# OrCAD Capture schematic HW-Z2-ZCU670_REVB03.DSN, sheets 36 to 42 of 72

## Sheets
36 037 Clock Generator: size Custom
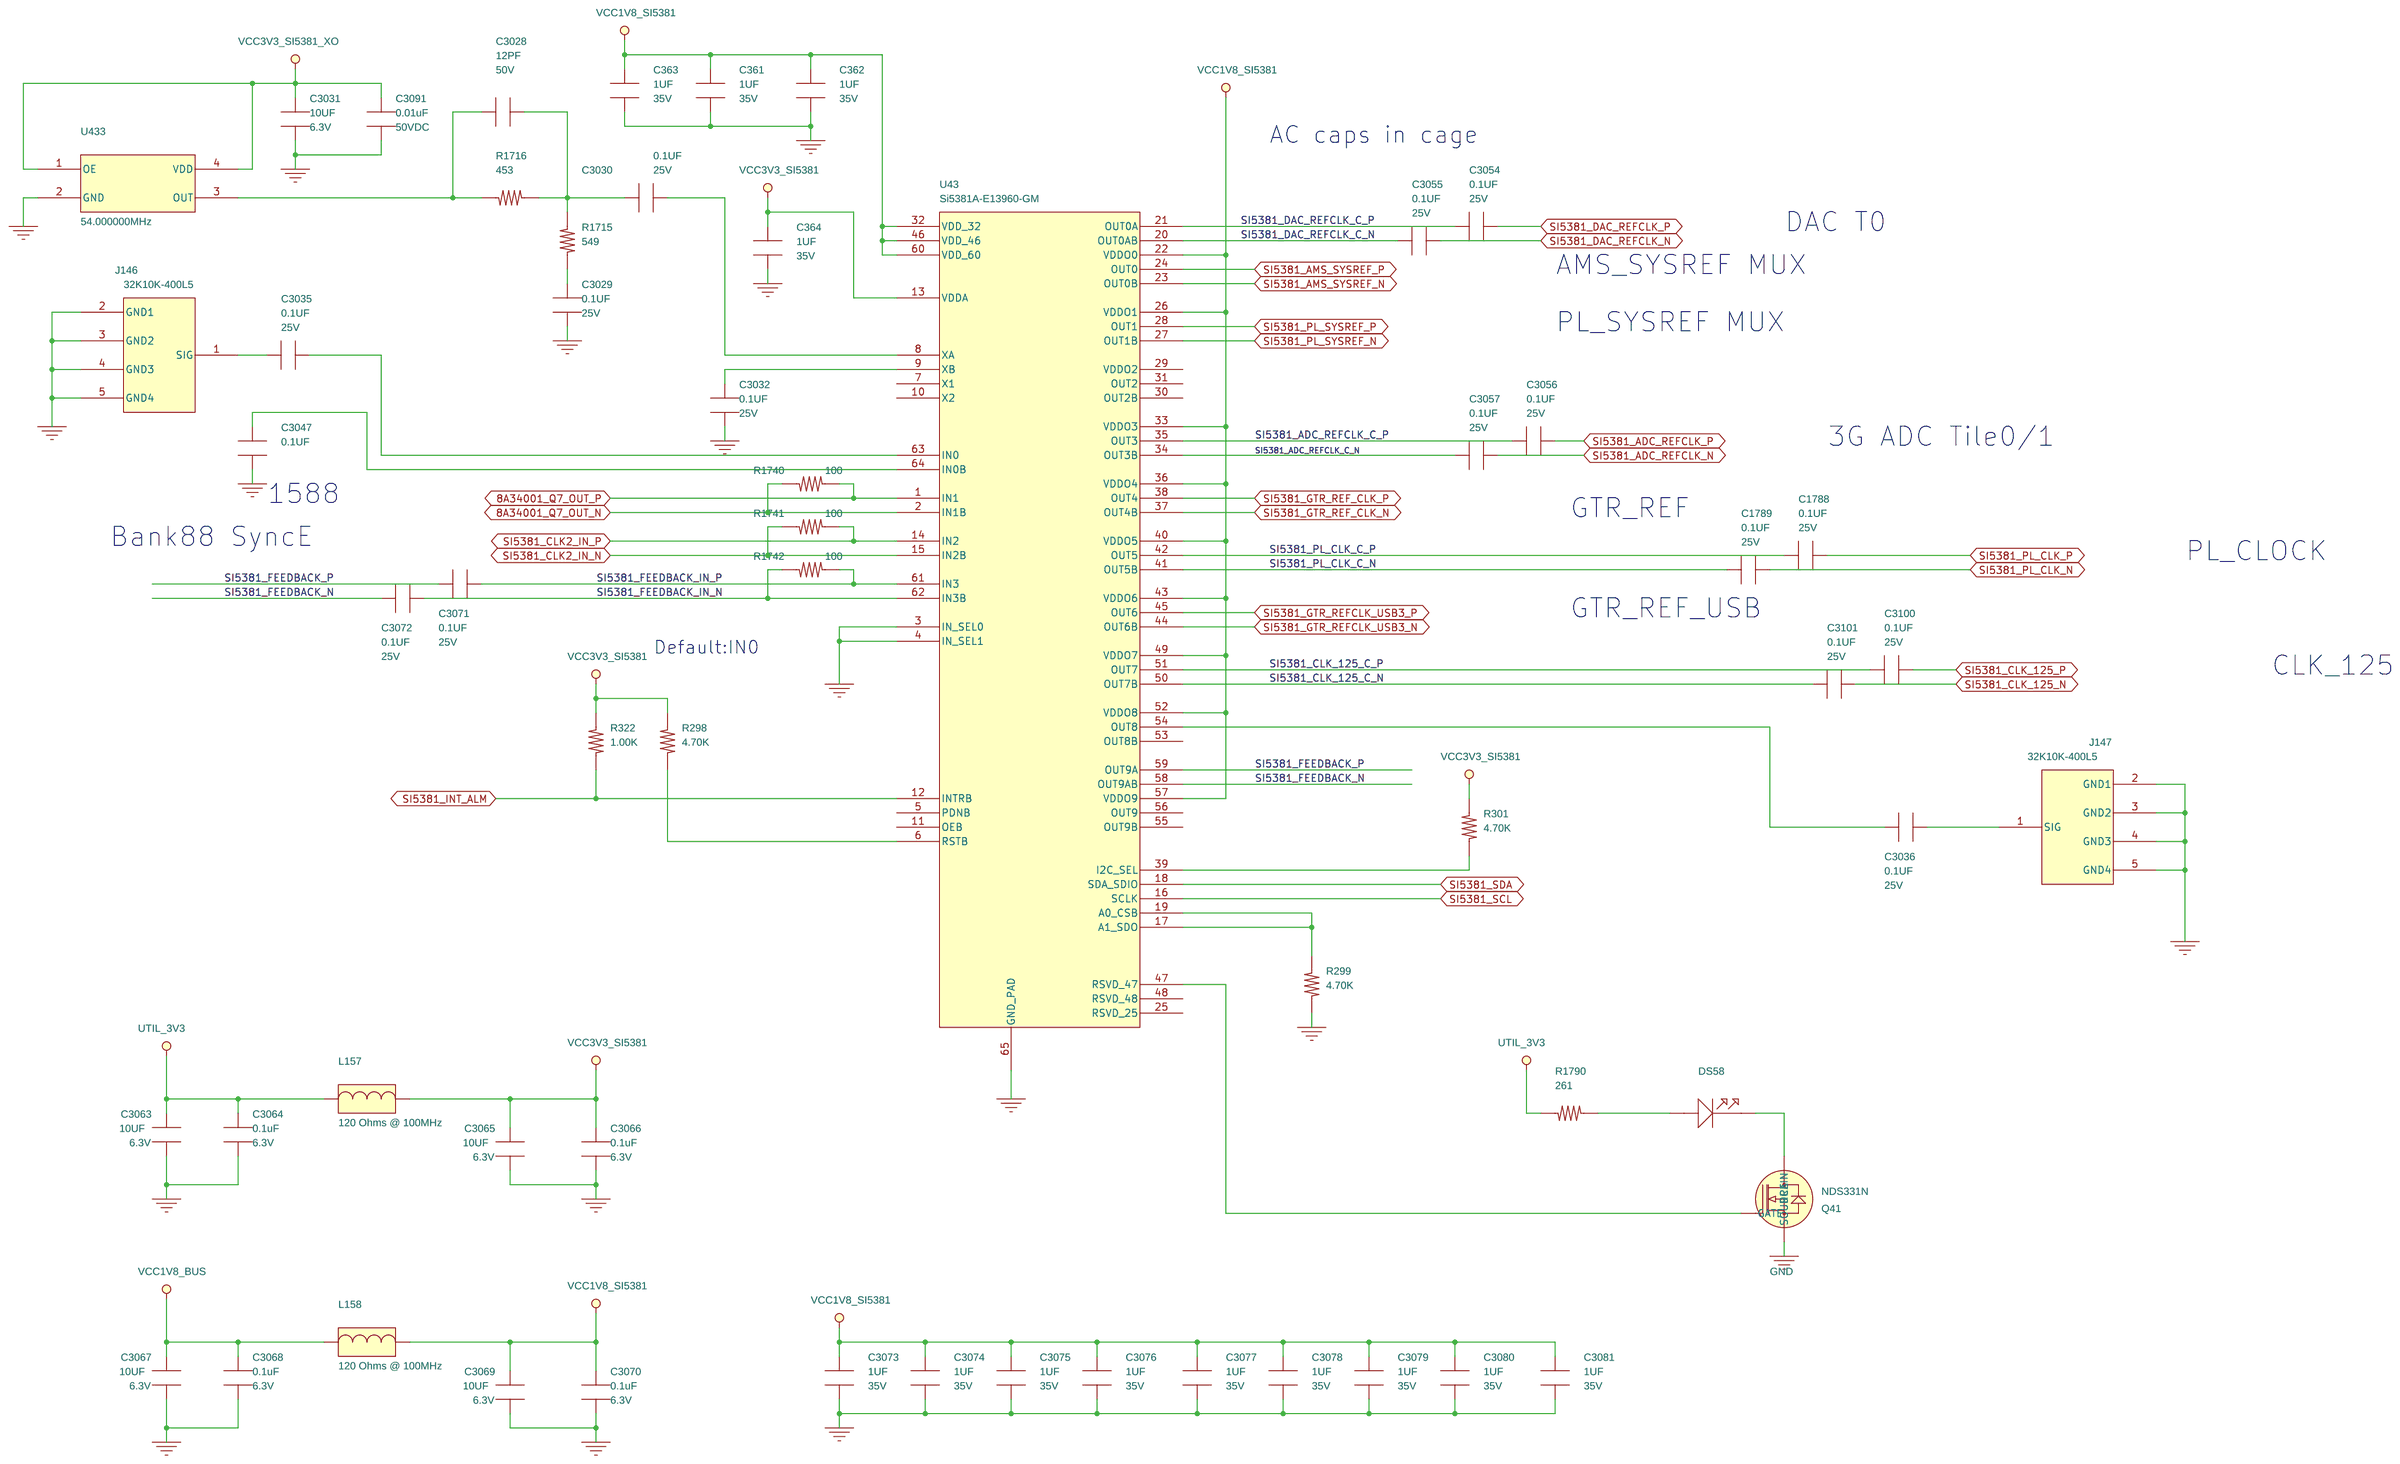
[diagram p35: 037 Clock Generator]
37 042 GPIO Switches Buttons: size Custom
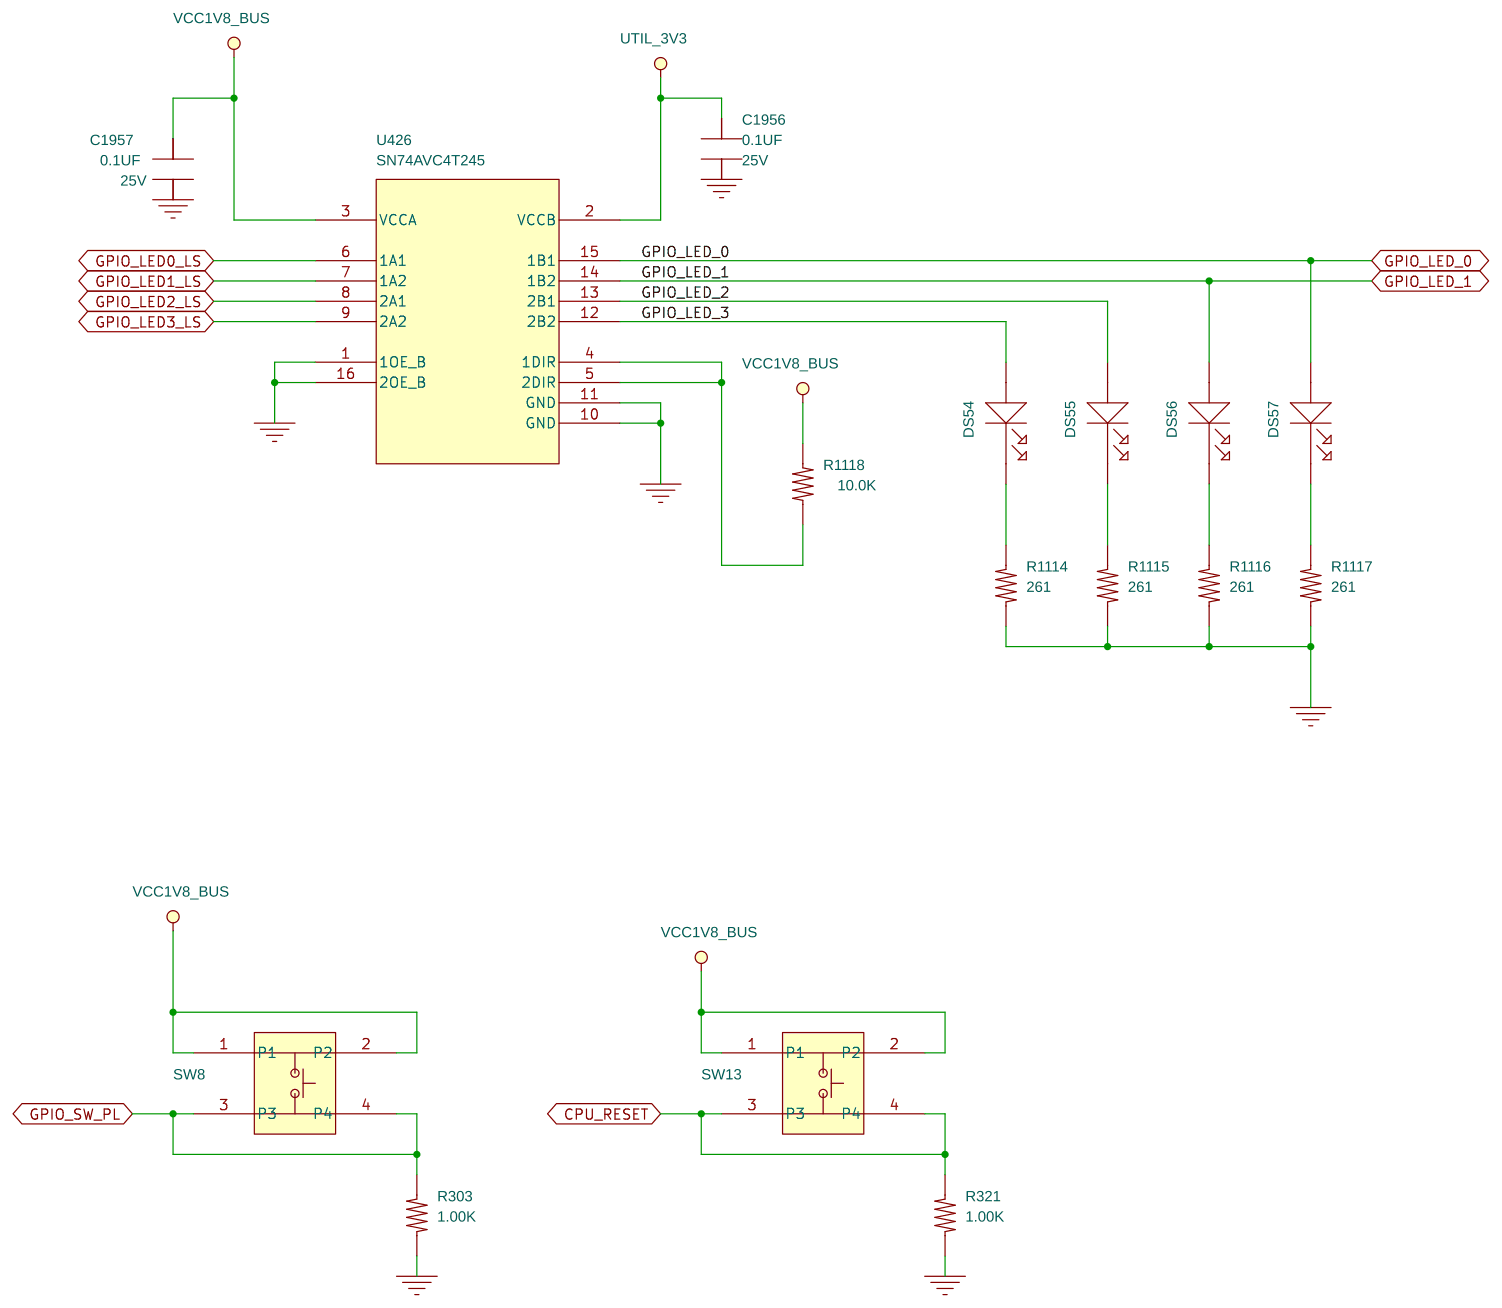
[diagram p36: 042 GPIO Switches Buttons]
38 035 1588 eCPRI CLK 2: size Custom
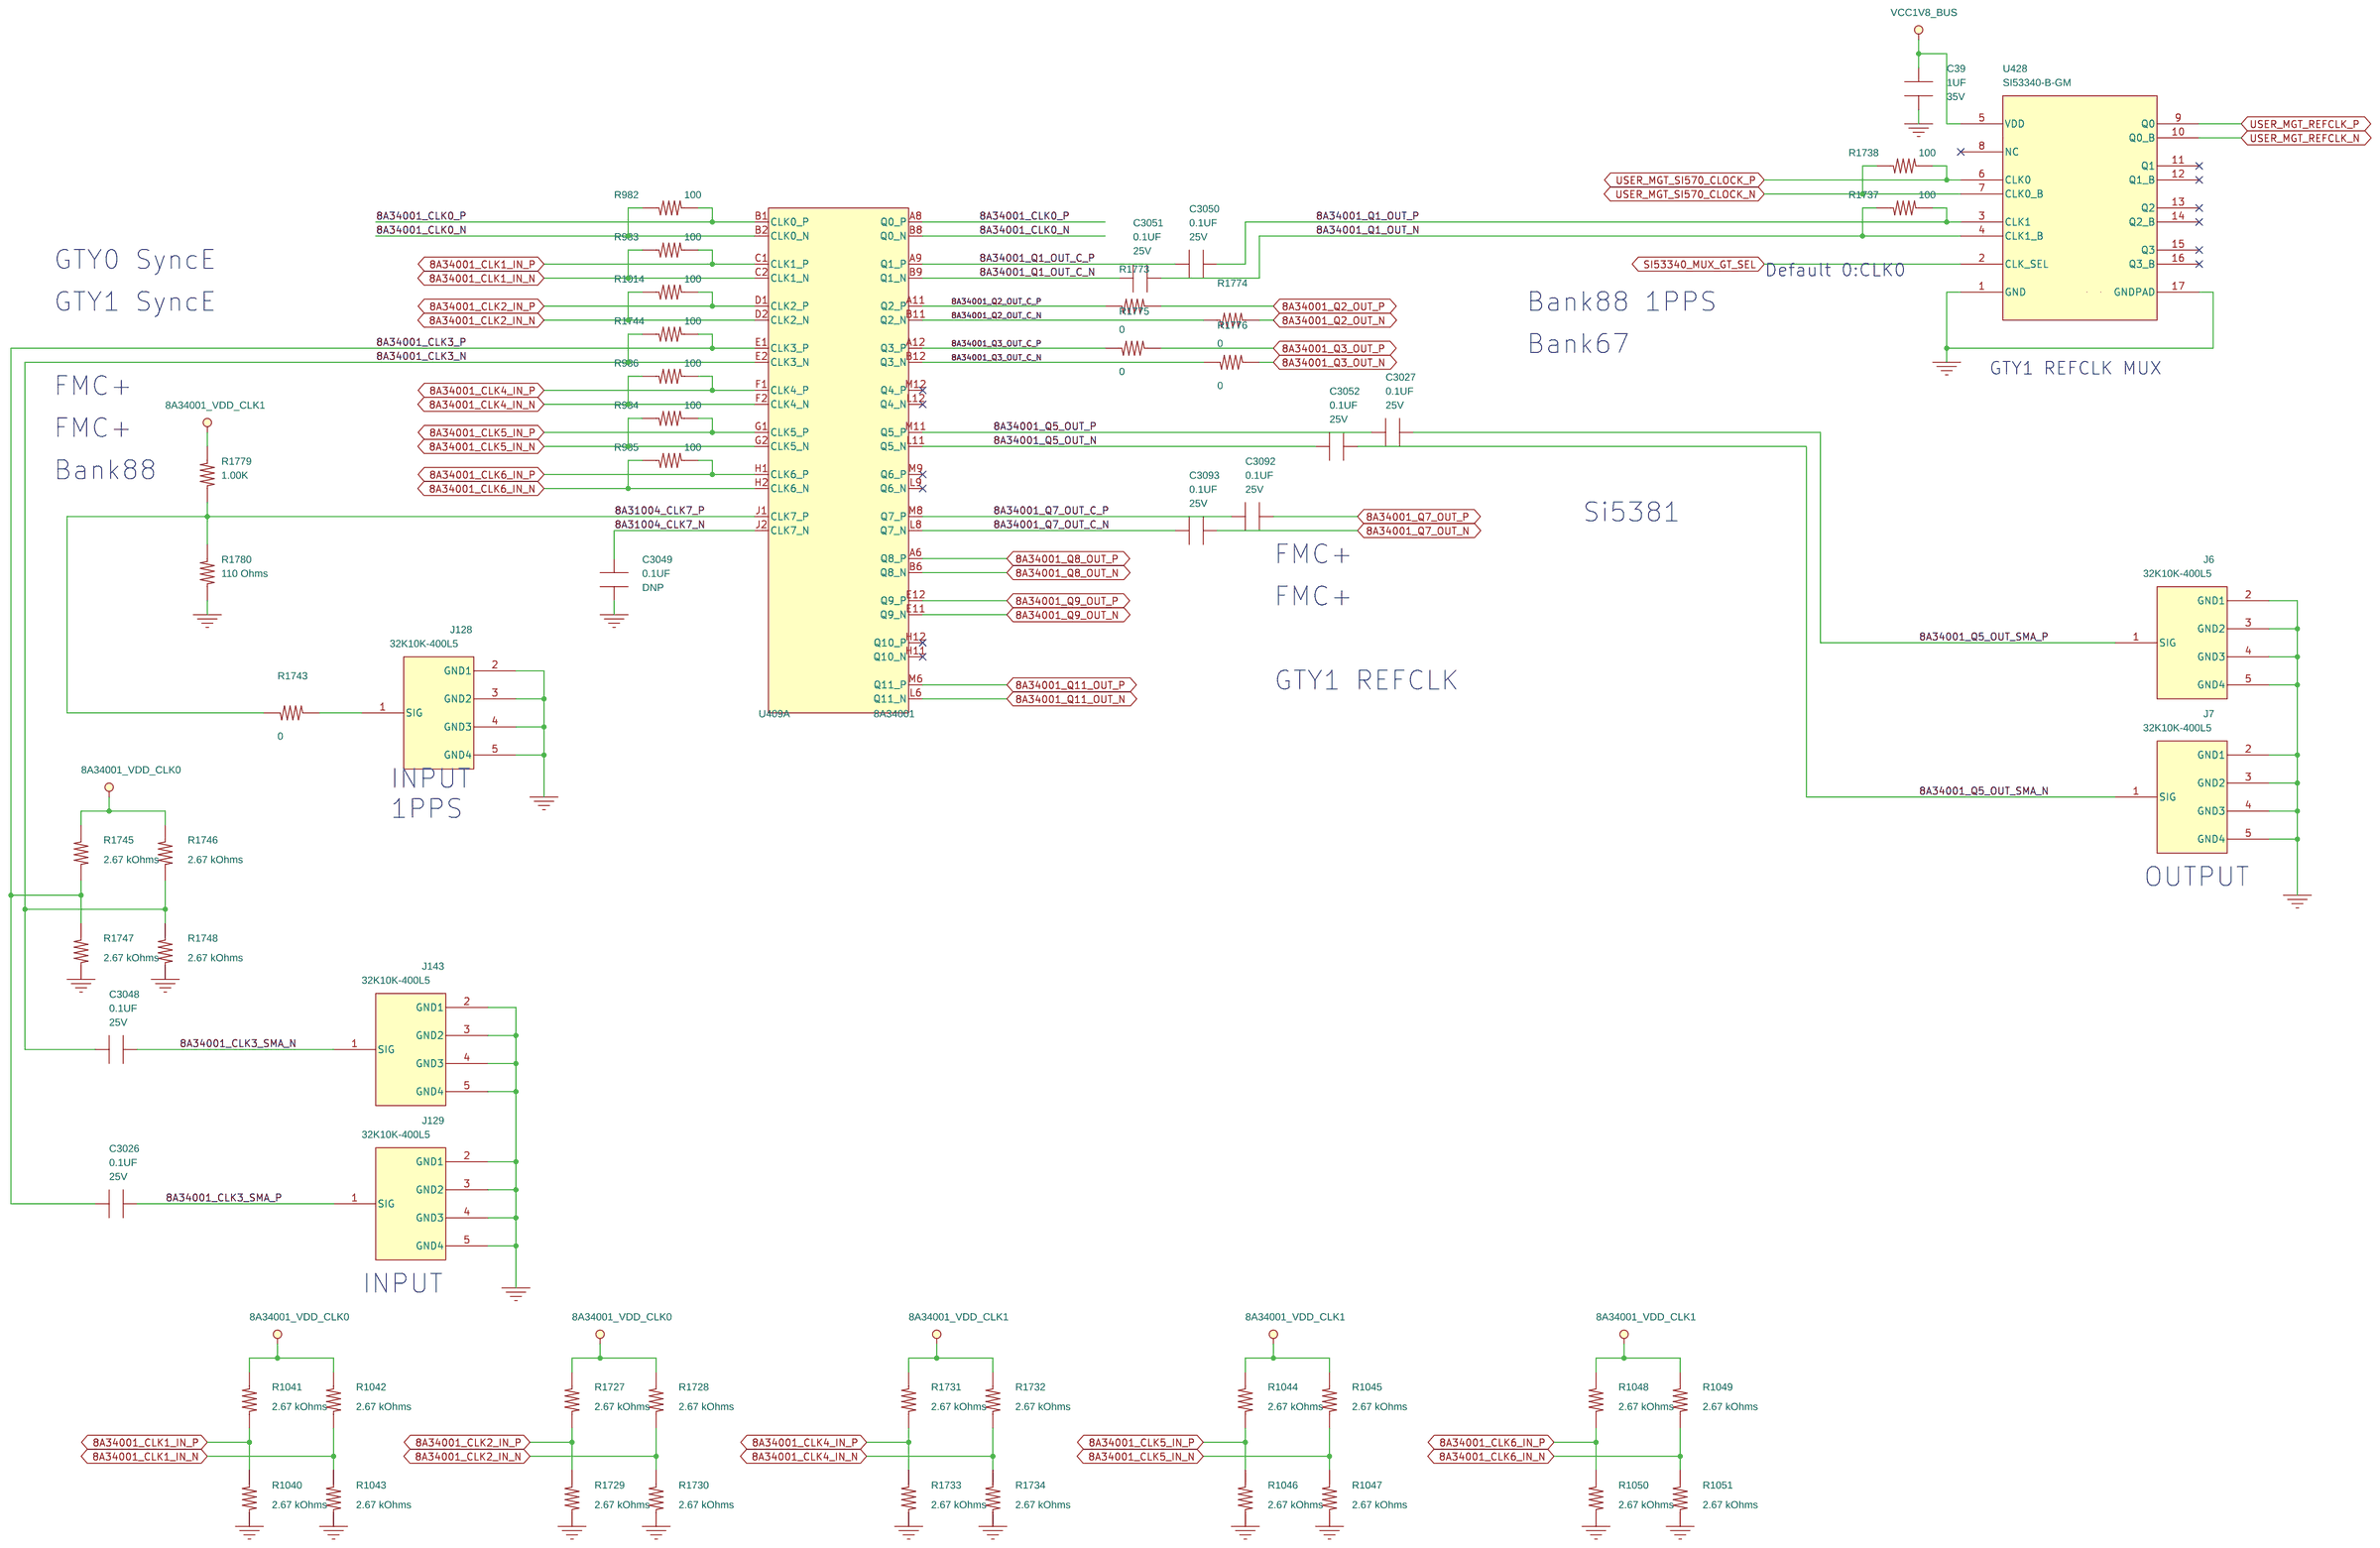
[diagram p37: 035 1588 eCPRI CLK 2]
39 039 Clock SWITCHES: size Custom
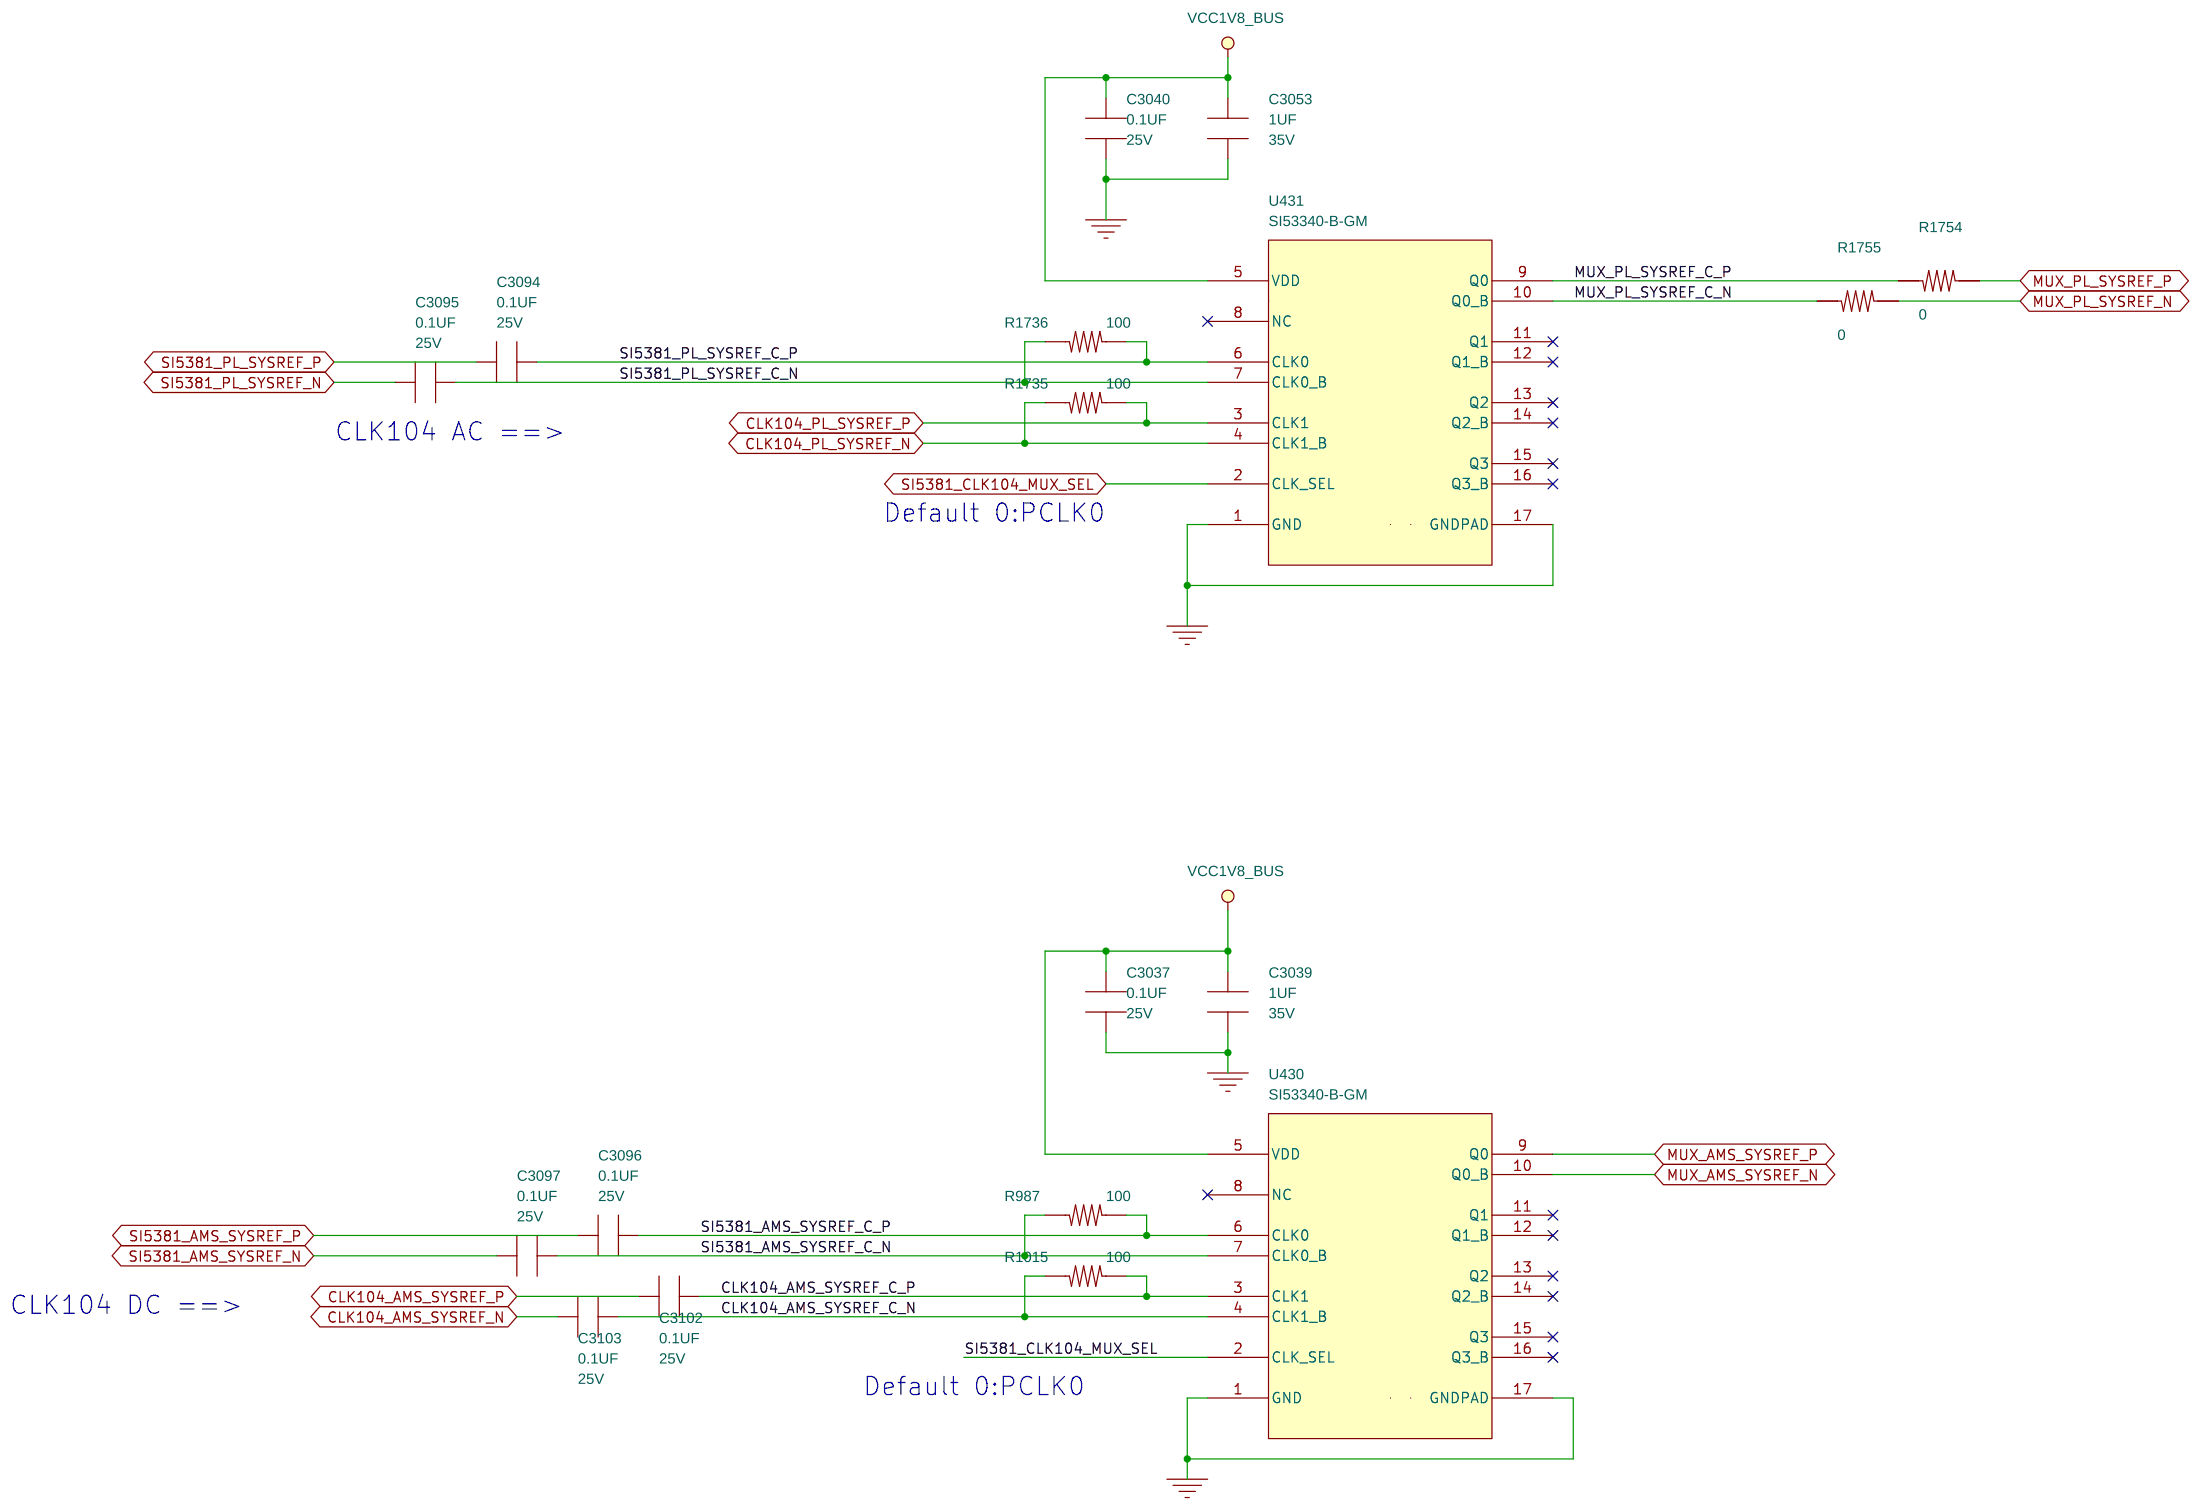
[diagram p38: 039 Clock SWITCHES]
40 040 PS DDR4 SODIMM: size Custom
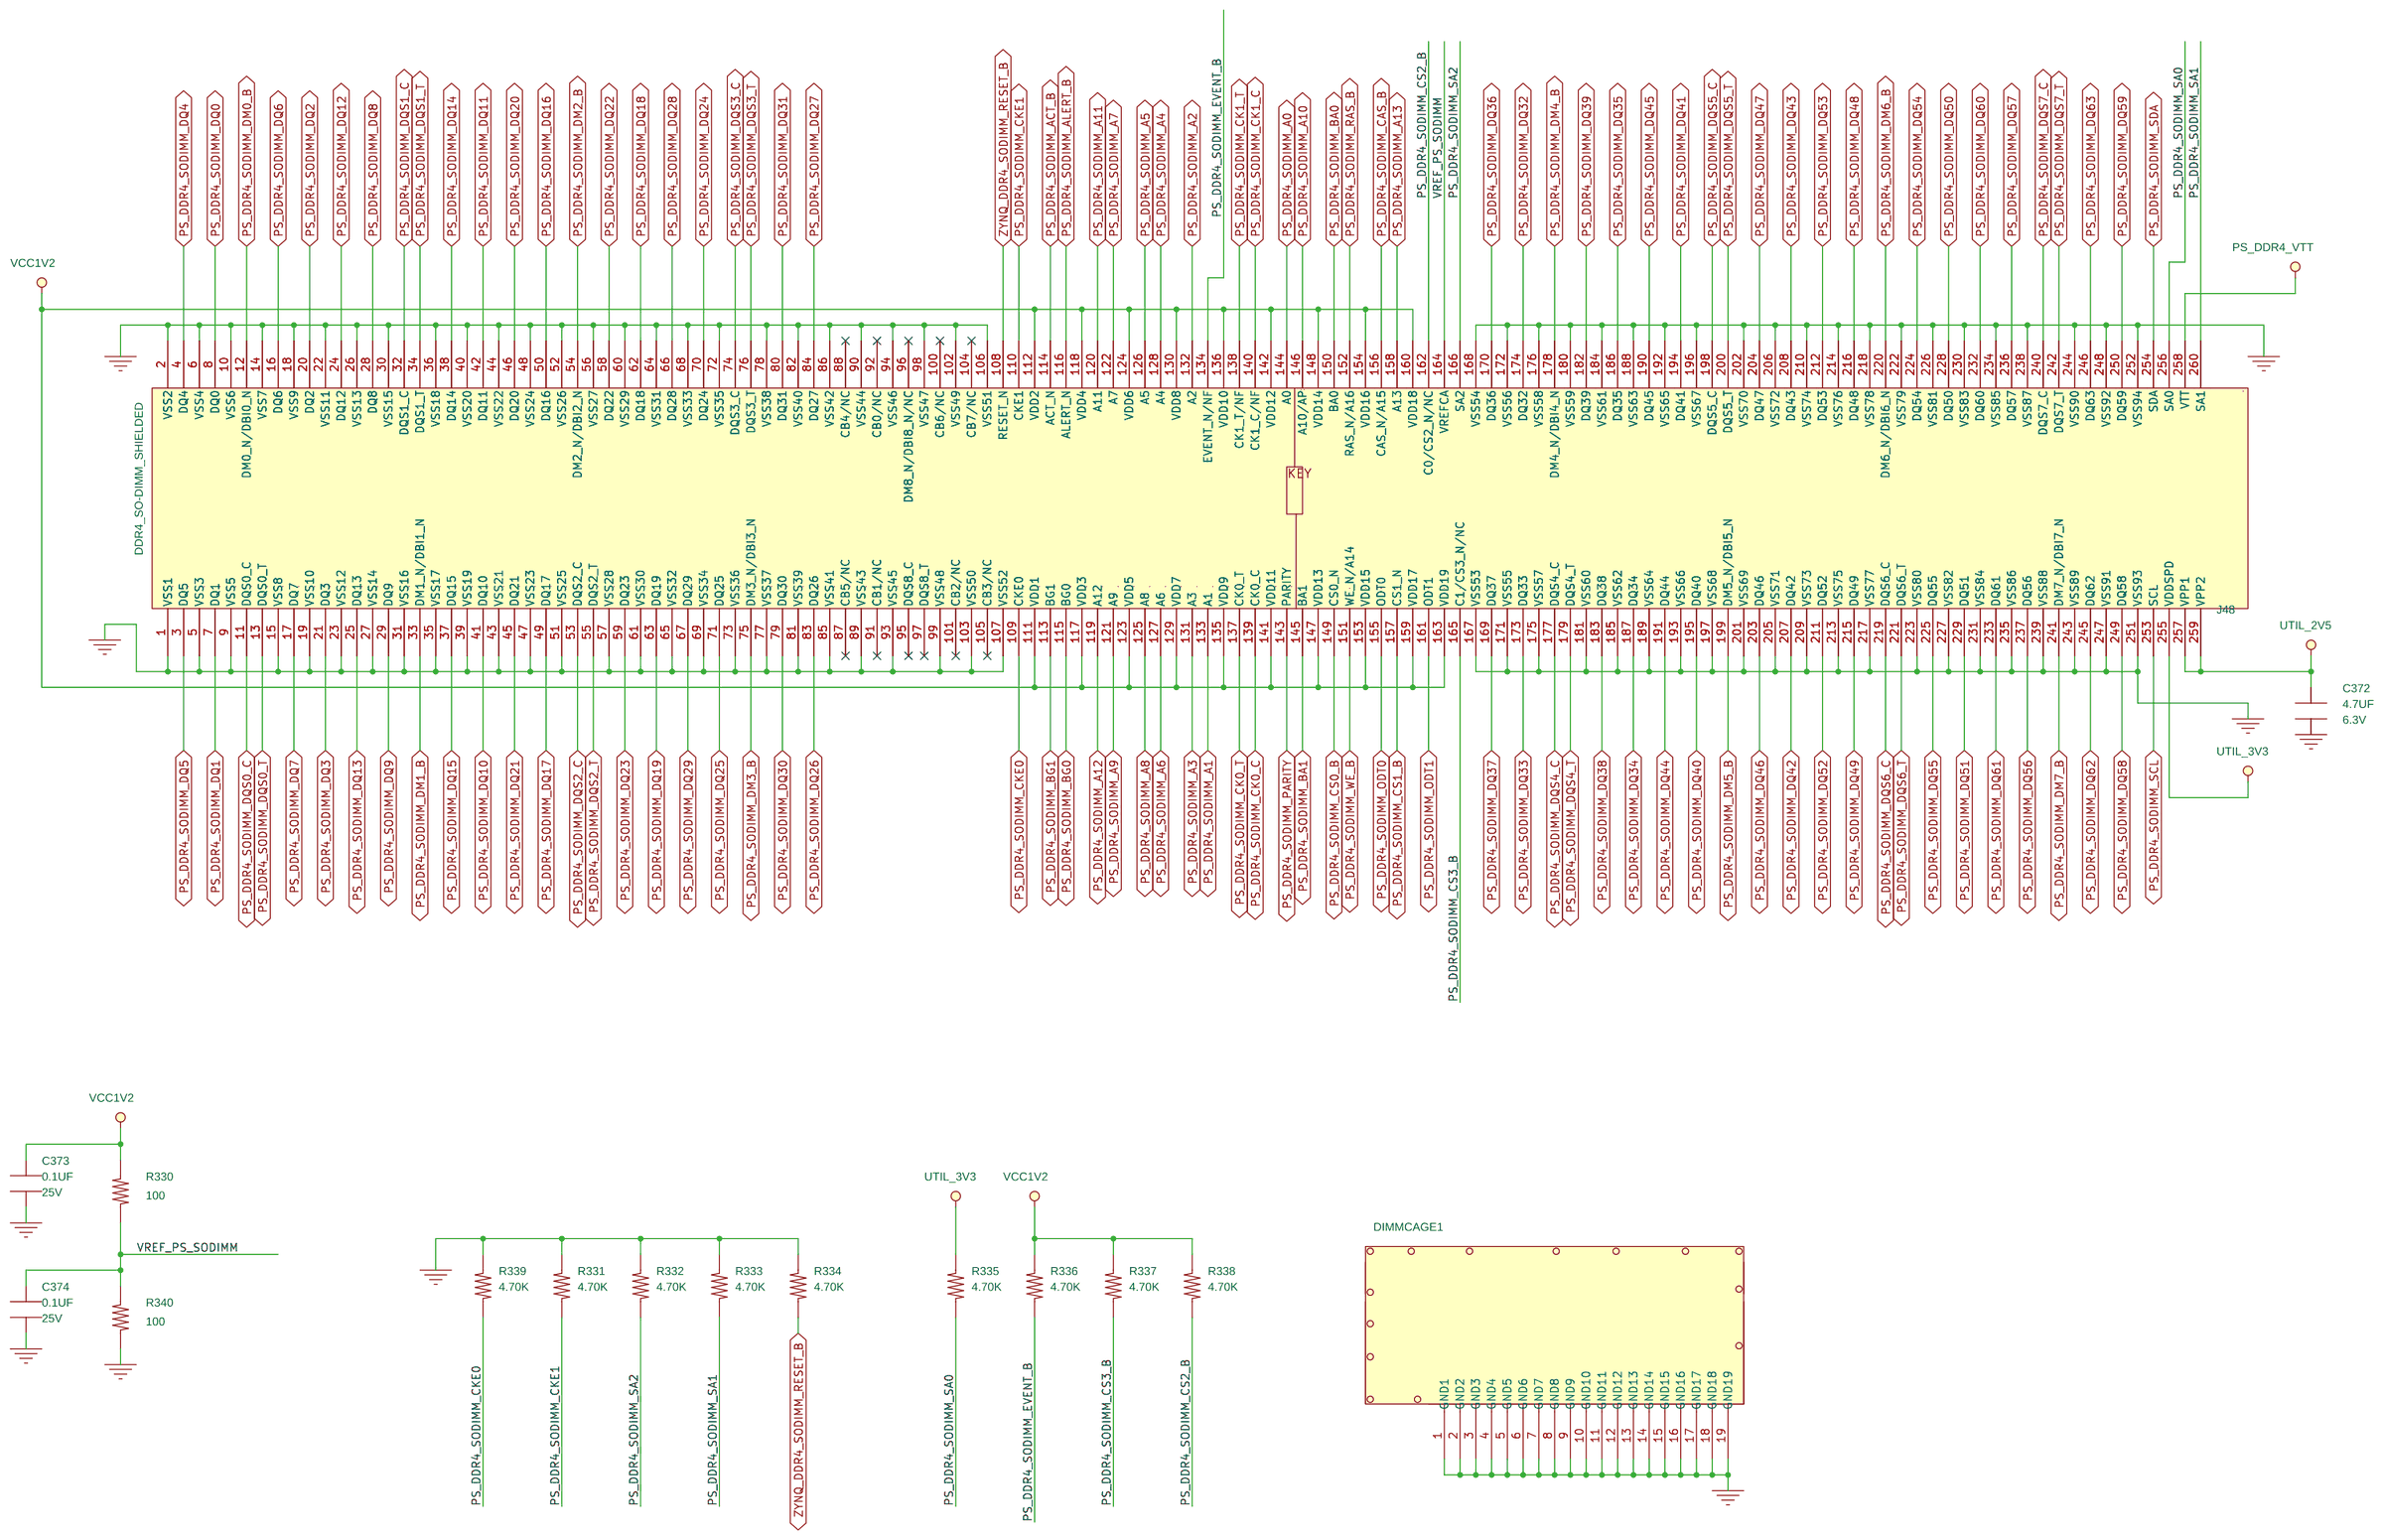
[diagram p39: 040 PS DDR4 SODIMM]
41 041 SODIMM Decoupling: size Custom
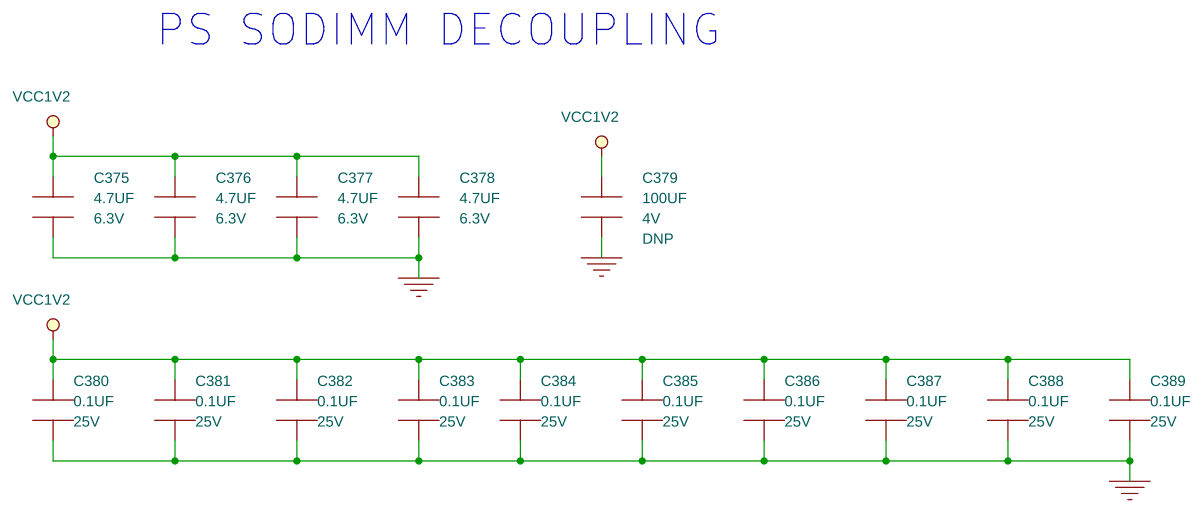
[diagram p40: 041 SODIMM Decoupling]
42 038 Programmable Clocks: size Custom
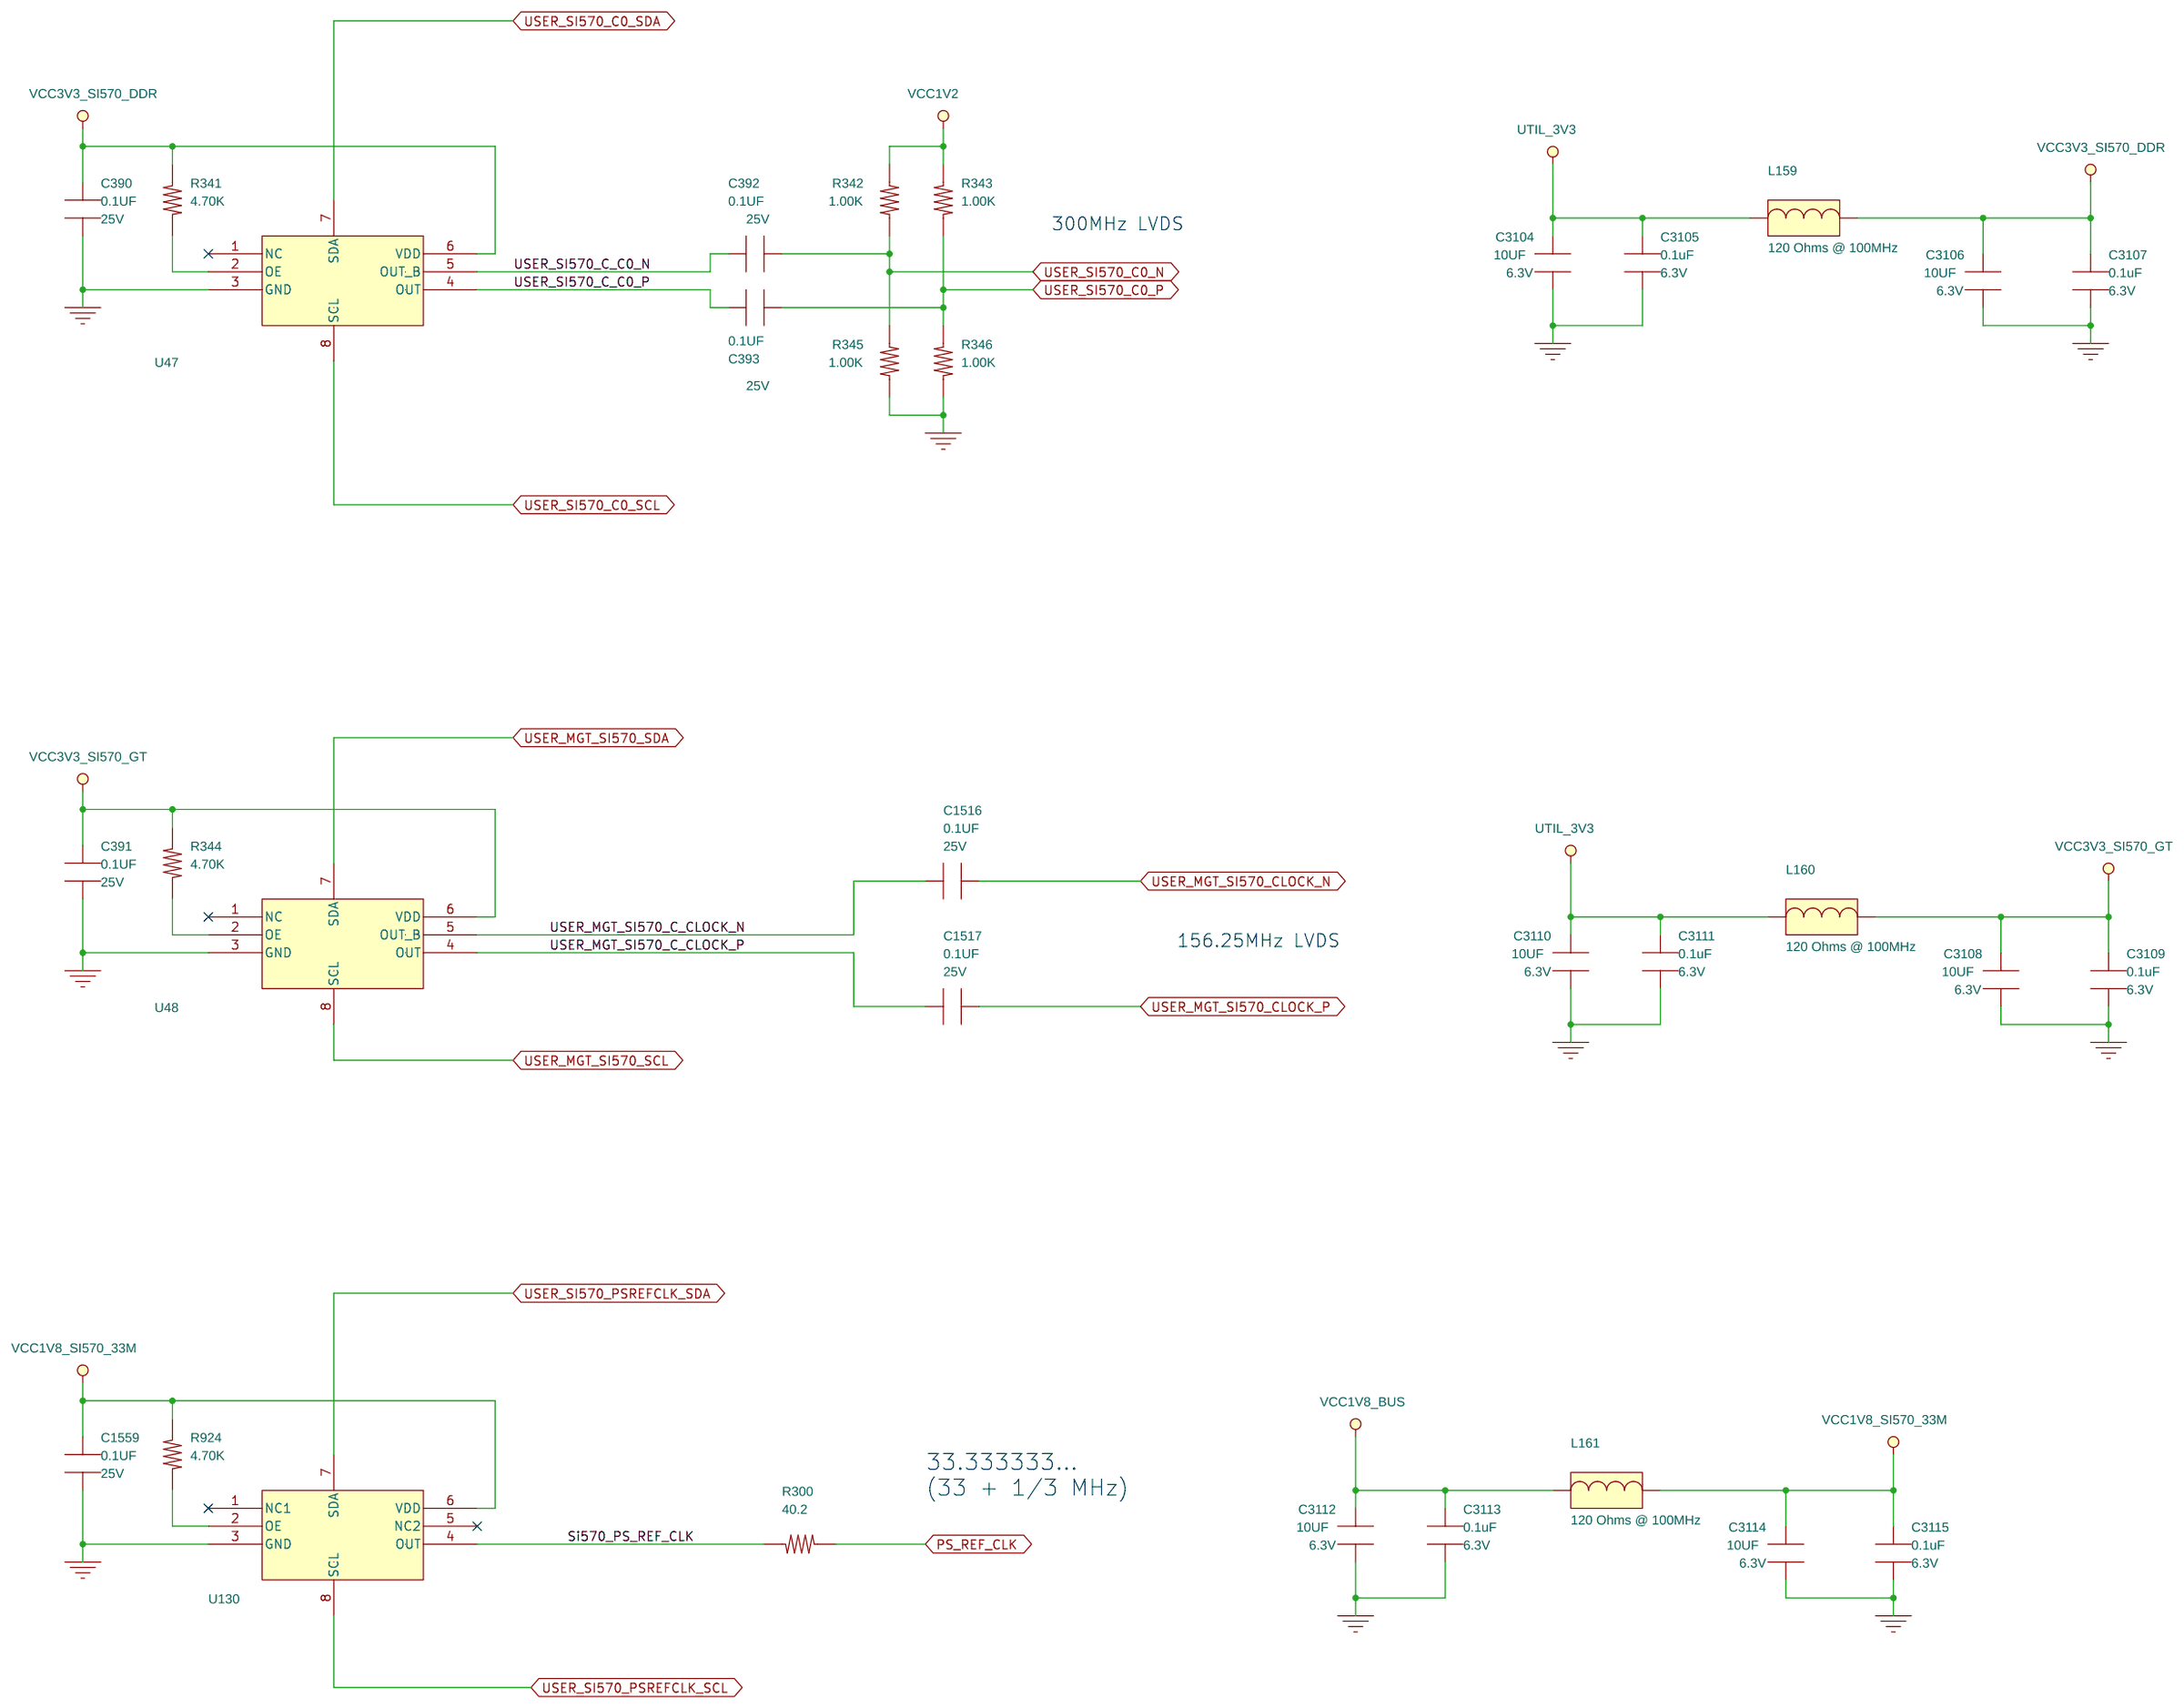
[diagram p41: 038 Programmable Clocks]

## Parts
sheet 035 1588 eCPRI CLK 2
C39  1UF  [CAPC100X50X60]
C3026  0.1UF  [CAPC60X30X40]
C3027  0.1UF  [CAPC60X30X40]
C3048  0.1UF  [CAPC60X30X40]
C3049  0.1UF  [CAPC60X30X40]
C3050  0.1UF  [CAPC60X30X40]
C3051  0.1UF  [CAPC60X30X40]
C3052  0.1UF  [CAPC60X30X40]
C3092  0.1UF  [CAPC60X30X40]
C3093  0.1UF  [CAPC60X30X40]
J6  32K10K-400L5  [32K10K_400_NEW]
J7  32K10K-400L5  [32K10K_400_NEW]
J128  32K10K-400L5  [32K10K_400_NEW]
J129  32K10K-400L5  [32K10K_400_NEW]
J143  32K10K-400L5  [32K10K_400_NEW]
R982  100  [RESC60X30X26]
R983  100  [RESC60X30X26]
R984  100  [RESC60X30X26]
R985  100  [RESC60X30X26]
R986  100  [RESC60X30X26]
R1014  100  [RESC60X30X26]
R1040  2.67 kOhms  [RESC60X30X26]
R1041  2.67 kOhms  [RESC60X30X26]
R1042  2.67 kOhms  [RESC60X30X26]
R1043  2.67 kOhms  [RESC60X30X26]
R1044  2.67 kOhms  [RESC60X30X26]
R1045  2.67 kOhms  [RESC60X30X26]
R1046  2.67 kOhms  [RESC60X30X26]
R1047  2.67 kOhms  [RESC60X30X26]
R1048  2.67 kOhms  [RESC60X30X26]
R1049  2.67 kOhms  [RESC60X30X26]
R1050  2.67 kOhms  [RESC60X30X26]
R1051  2.67 kOhms  [RESC60X30X26]
R1727  2.67 kOhms  [RESC60X30X26]
R1728  2.67 kOhms  [RESC60X30X26]
R1729  2.67 kOhms  [RESC60X30X26]
R1730  2.67 kOhms  [RESC60X30X26]
R1731  2.67 kOhms  [RESC60X30X26]
R1732  2.67 kOhms  [RESC60X30X26]
R1733  2.67 kOhms  [RESC60X30X26]
R1734  2.67 kOhms  [RESC60X30X26]
R1737  100  [RESC60X30X26]
R1738  100  [RESC60X30X26]
R1743  0  [RESC60X30X26]
R1744  100  [RESC60X30X26]
R1745  2.67 kOhms  [RESC60X30X26]
R1746  2.67 kOhms  [RESC60X30X26]
R1747  2.67 kOhms  [RESC60X30X26]
R1748  2.67 kOhms  [RESC60X30X26]
R1773  0  [RESC60X30X26]
R1774  0  [RESC60X30X26]
R1775  0  [RESC60X30X26]
R1776  0  [RESC60X30X26]
R1779  1.00K  [RESC100X50X40]
R1780  110 Ohms  [RESC100X50X40]
U409  8A34001  [CABGA_144P80]  (sections A,B,C)
U428  SI53340-B-GM  [QFN16_SI_3X3MM]
sheet 037 Clock Generator
C361  1UF  [CAPC100X50X60]
C362  1UF  [CAPC100X50X60]
C363  1UF  [CAPC100X50X60]
C364  1UF  [CAPC100X50X60]
C1788  0.1UF  [CAPC60X30X40]
C1789  0.1UF  [CAPC60X30X40]
C3028  12PF  [CAPC100X50X55]
C3029  0.1UF  [CAPC100X50X55]
C3030  0.1UF  [CAPC100X50X55]
C3031  10UF  [CAPC100X50X70]
C3032  0.1UF  [CAPC100X50X55]
C3035  0.1UF  [CAPC60X30X40]
C3036  0.1UF  [CAPC60X30X40]
C3047  0.1UF  [CAPC60X30X40]
C3054  0.1UF  [CAPC60X30X40]
C3055  0.1UF  [CAPC60X30X40]
C3056  0.1UF  [CAPC60X30X40]
C3057  0.1UF  [CAPC60X30X40]
C3063  10UF  [CAPC100X50X70]
C3064  0.1uF  [CAPC60X30X33]
C3065  10UF  [CAPC100X50X70]
C3066  0.1uF  [CAPC60X30X33]
C3067  10UF  [CAPC100X50X70]
C3068  0.1uF  [CAPC60X30X33]
C3069  10UF  [CAPC100X50X70]
C3070  0.1uF  [CAPC60X30X33]
C3071  0.1UF  [CAPC60X30X40]
C3072  0.1UF  [CAPC60X30X40]
C3073  1UF  [CAPC100X50X60]
C3074  1UF  [CAPC100X50X60]
C3075  1UF  [CAPC100X50X60]
C3076  1UF  [CAPC100X50X60]
C3077  1UF  [CAPC100X50X60]
C3078  1UF  [CAPC100X50X60]
C3079  1UF  [CAPC100X50X60]
C3080  1UF  [CAPC100X50X60]
C3081  1UF  [CAPC100X50X60]
C3091  0.01uF  [CAPC100X50X55]
C3100  0.1UF  [CAPC60X30X40]
C3101  0.1UF  [CAPC60X30X40]
DS58  LED-GRN-SMT  [LED_0603]
J146  32K10K-400L5  [32K10K_400_NEW]
J147  32K10K-400L5  [32K10K_400_NEW]
L157  120 Ohms @ 100MHz  [FB_BLM15PX121SN1D]
L158  120 Ohms @ 100MHz  [FB_BLM15PX121SN1D]
Q41  NDS331N  [SOT_23]
R298  4.70K  [RESC100X50X40]
R299  4.70K  [RESC100X50X40]
R301  4.70K  [RESC100X50X40]
R322  1.00K  [RESC100X50X40]
R1715  549  [RESC100X50X40]
R1716  453  [RESC100X50X40]
R1740  100  [RESC60X30X26]
R1741  100  [RESC60X30X26]
R1742  100  [RESC60X30X26]
R1790  261  [RESC100X50X40]
U43  Si5381A-E13960-GM  [OSC_SI341B_64P]
U433  54.000000MHz  [OSC320X250X110-4]
sheet 038 Programmable Clocks
C390  0.1UF  [CAPC100X50X55]
C391  0.1UF  [CAPC100X50X55]
C392  0.1UF  [CAPC100X50X55]
C393  0.1UF  [CAPC100X50X55]
C1516  0.1UF  [CAPC100X50X55]
C1517  0.1UF  [CAPC100X50X55]
C1559  0.1UF  [CAPC100X50X55]
C3104  10UF  [CAPC100X50X70]
C3105  0.1uF  [CAPC60X30X33]
C3106  10UF  [CAPC100X50X70]
C3107  0.1uF  [CAPC60X30X33]
C3108  10UF  [CAPC100X50X70]
C3109  0.1uF  [CAPC60X30X33]
C3110  10UF  [CAPC100X50X70]
C3111  0.1uF  [CAPC60X30X33]
C3112  10UF  [CAPC100X50X70]
C3113  0.1uF  [CAPC60X30X33]
C3114  10UF  [CAPC100X50X70]
C3115  0.1uF  [CAPC60X30X33]
L159  120 Ohms @ 100MHz  [FB_BLM15PX121SN1D]
L160  120 Ohms @ 100MHz  [FB_BLM15PX121SN1D]
L161  120 Ohms @ 100MHz  [FB_BLM15PX121SN1D]
R300  40.2  [RESC100X50X40]
R341  4.70K  [RESC100X50X40]
R342  1.00K  [RESC100X50X40]
R343  1.00K  [RESC100X50X40]
R344  4.70K  [RESC100X50X40]
R345  1.00K  [RESC100X50X40]
R346  1.00K  [RESC100X50X40]
R924  4.70K  [RESC100X50X40]
U47  10MHZ_TO_810MHZ  [SI570]
U48  10MHZ_TO_810MHZ  [SI570]
U130  10MHZ-160MHZ  [SI570]
sheet 039 Clock SWITCHES
C3037  0.1UF  [CAPC100X50X55]
C3039  1UF  [CAPC100X50X60]
C3040  0.1UF  [CAPC100X50X55]
C3053  1UF  [CAPC100X50X60]
C3094  0.1UF  [CAPC60X30X40]
C3095  0.1UF  [CAPC60X30X40]
C3096  0.1UF  [CAPC60X30X40]
C3097  0.1UF  [CAPC60X30X40]
C3102  0.1UF  [CAPC60X30X40]
C3103  0.1UF  [CAPC60X30X40]
R987  100  [RESC60X30X26]
R1015  100  [RESC60X30X26]
R1735  100  [RESC60X30X26]
R1736  100  [RESC60X30X26]
R1754  0  [RESC60X30X26]
R1755  0  [RESC60X30X26]
U430  SI53340-B-GM  [QFN16_SI_3X3MM]
U431  SI53340-B-GM  [QFN16_SI_3X3MM]
sheet 040 PS DDR4 SODIMM
C372  4.7UF  [CAPC100X50X60]
C373  0.1UF  [CAPC100X50X55]
C374  0.1UF  [CAPC100X50X55]
DIMMCAGE1  SODIMM_CAGE  [SODIMM_CAGE]
J48  DDR4_SO-DIMM_SHIELDED  [DDR4_SO-DIMM_SHIELDED]
R330  100  [RESC100X50X40]
R331  4.70K  [RESC100X50X40]
R332  4.70K  [RESC100X50X40]
R333  4.70K  [RESC100X50X40]
R334  4.70K  [RESC100X50X40]
R335  4.70K  [RESC100X50X40]
R336  4.70K  [RESC100X50X40]
R337  4.70K  [RESC100X50X40]
R338  4.70K  [RESC100X50X40]
R339  4.70K  [RESC100X50X40]
R340  100  [RESC100X50X40]
sheet 041 SODIMM Decoupling
C375  4.7UF  [CAPC100X50X60]
C376  4.7UF  [CAPC100X50X60]
C377  4.7UF  [CAPC100X50X60]
C378  4.7UF  [CAPC100X50X60]
C379  100UF  [CAPC200X125X145]
C380  0.1UF  [CAPC100X50X55]
C381  0.1UF  [CAPC100X50X55]
C382  0.1UF  [CAPC100X50X55]
C383  0.1UF  [CAPC100X50X55]
C384  0.1UF  [CAPC100X50X55]
C385  0.1UF  [CAPC100X50X55]
C386  0.1UF  [CAPC100X50X55]
C387  0.1UF  [CAPC100X50X55]
C388  0.1UF  [CAPC100X50X55]
C389  0.1UF  [CAPC100X50X55]
sheet 042 GPIO Switches Buttons
C1956  0.1UF  [CAPC100X50X55]
C1957  0.1UF  [CAPC100X50X55]
DS54  LED-GRN-SMT  [LED_0603]
DS55  LED-GRN-SMT  [LED_0603]
DS56  LED-GRN-SMT  [LED_0603]
DS57  LED-GRN-SMT  [LED_0603]
R303  1.00K  [RESC100X50X40]
R321  1.00K  [RESC100X50X40]
R1114  261  [RESC100X50X40]
R1115  261  [RESC100X50X40]
R1116  261  [RESC100X50X40]
R1117  261  [RESC100X50X40]
R1118  10.0K  [RESC100X50X40]
SW8  TL3301EF100QG  [SW_TL3301_G_4P]
SW13  TL3301EF100QG  [SW_TL3301_G_4P]
U426  SN74AVC4T245  [QFN_RSV_16]

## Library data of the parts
C39 C361-C364 C3039 C3053 C3073-C3081 = CAP_NP: Cap Cer 1uF 10% 35V X5R 0402; ALT_SYMBOLS: CAPC100X50X60RND; Agile Part Number: CAP-00165-01; CIP Link: http://xsjbrdwin1/CIP-E/Component/Index/All?pn=100192; Dielectric Type: X5R; OWNER: 3709; PRICE: 0.04; Part Type: CERAMIC; PartType: CERAMIC; ROHS: Yes; Tolerance: 10%; Voltage: 35V; barcode: 100192
C1788 C1789 C3026 C3027 C3035 C3036 C3048 C3050-C3052 C3054-C3057 C3071 C3072 C3092-C3097 C3100-C3103 = CAP_NP: Cap Cer 100nF 10% 25V X5R 0201; ALT_SYMBOLS: CAPC60X30X40RND; Agile Part Number: CAP-00142-01; Barcode: 100161; CIP Link: http://xsjbrdwin1/CIP-E/Component/Index/All?pn=100161; Dielectric Type: X5R; Part Type: CERAMIC; Tolerance: 10%; Voltage: 25V
C3049 = CAP_NP: Cap Cer 100nF 10% 25V X5R 0201; ALT_SYMBOLS: CAPC60X30X40RND; ASSEMBLY_OPTIONS: DNP; Agile Part Number: CAP-00142-01; Barcode: 100161; CIP Link: http://xsjbrdwin1/CIP-E/Component/Index/All?pn=100161; Dielectric Type: X5R; Part Type: CERAMIC; Tolerance: 10%; Voltage: 25V
J6 J7 J128 J129 J143 J146 J147 = SMA-5PIN: Conn Rcpt SMA Vert 50R 12.4GHz SMT/TH; ALT_SYMBOLS: 32K10K_400_3M_73251_DUAL; Agile Part Number: CON-00180-01; Barcode: 400125; CIP Link: http://xsjbrdwin1/CIP-E/Component/Index/All?pn=400125; OWNER: 4001; PRICE: 3.89; Part Type: SMA; PartType: SMA; Pins: 5PINS; ROHS: Yes
R982-R987 R1014 R1015 R1735-R1738 R1740-R1742 R1744 = RES: Res 100R 1% 1/20W 200PPM 25V 0201; Agile Part Number: RES-00129-01; Barcode: 200116; CIP Link: http://xsjbrdwin1/CIP-E/Component/Index/All?pn=200116; Part Type: SMT - 1%; Rated Power: 1/20W; Tolerance: 1%
R1040-R1051 R1727-R1734 R1745-R1748 = RES: Res 2K67 1% 1/20W 200PPM 25V 0201; Agile Part Number: RES-00598-01; Barcode: 20000076; CIP Link: http://xsjbrdwin1/CIP-E/Component/Index/All?pn=20000076; Part Type: SMT - 1%; Rated Power: 0.05W, 1/20W; Tolerance: 1%
R1743 R1754 R1755 R1773-R1776 = RES: Res 0R 50mR 500mA 0201; ALT_SYMBOLS: RESC60X30X26RND; Agile Part Number: RES-00347-01; Barcode: 200383; CIP Link: http://xsjbrdwin1/CIP-E/Component/Index/All?pn=200383; Part Type: RESISTOR; Rated Power: 1/20W; Tolerance: NA
R303 R321 R322 R342 R343 R345 R346 R1779 = RES: Res 1K 1% 1/16W 100PPM 50V 0402; ALT_SYMBOLS: RESC100X50X40RND; Agile Part Number: RES-00027-01; Barcode: 200098; CIP Link: http://xsjbrdwin1/CIP-E/Component/Index/All?pn=200098; OWNER: 4001; PRICE: 0; Part Type: SMT - 1%; PartType: SMT - 1%; Power: 1/16W; ROHS: Yes; Rated Power: 1/16W; Tolerance: 1%; primarykey: 7
R1780 = RES: Res 110R 1% 1/16W 100PPM 50V 0402; Agile Part Number: RES-00511-01; Barcode: 20000030; CIP Link: http://xsjbrdwin1/CIP-E/Component/Index/All?pn=20000030; Part Type: SMT - 1%; Rated Power: 1/16W; Tolerance: 1%
U409 = 8A34001: IC Synch Man Unit 8-Ch 24 LVCMOS Outs CABGA-144; Agile Part Number: ICS-00510-01; Barcode: 50000042; CIP Link: http://xsjbrdwin1/CIP-E/Component/Index/All?pn=50000042; Part Type: Unassigned Part Type
U428 U430 U431 = SI53340: IC BUFFER 2:4 LVDS MUX 16QFN; Agile Part Number: ICS-00217-01; Barcode: 500294; CIP Link: http://xsjbrdwin1/CIP-E/Component/Index/All?pn=500294; Part Type: CLOCK MULTIPLIER
C3028 = CAP_NP: Cap Cer 12pF 5% 50V C0G 0402; ALT_SYMBOLS: (0402,C402-25,CAPC100X50X55L25NRND,CAPC100X50X55L30NRND,CAPC100X50X55L30N); Agile Part Number: CAP-00095-01; Barcode: 100092; CIP Link: http://xsjbrdwin1/CIP-E/Component/Index/All?pn=100092; Dielectric Type: NP0; Part Type: CERAMIC; Tolerance: 5%; Voltage: 50V
C373 C374 C380-C393 C1559 C1956 C1957 C3029 C3030 C3032 C3037 C3040 = CAP_NP: Cap Cer 100nF 10% 25V X5R 0402; ALT_SYMBOLS: CAPC100X50X55RND; Agile Part Number: CAP-00068-01; CIP Link: http://xsjbrdwin1/CIP-E/Component/Index/All?pn=100040; Dielectric Type: X5R; OWNER: 4001; PRICE: 0.01; Part Type: CERAMIC; PartType: CERAMIC; ROHS: Yes; Tolerance: 10%; Voltage: 25V; barcode: 100040
C3031 = CAP_NP: Cap Cer 10uF 20%  6.3V X6S 0402; ALT_SYMBOLS: CAPC100X50X55RND; Agile Part Number: CAP-00035-01; CIP Link: http://xsjbrdwin1/CIP-E/Component/Index/All?pn=100268; Dielectric Type: X6S; OWNER: 3670; PRICE: 0.04; Part Type: CERAMIC; PartType: CERAMIC; ROHS: Yes; Tolerance: 20%; Voltage: 6.3V; barcode: 100268
C3047 = CAP_NP: Cap Cer 100nF 10% 25V X5R 0201; ALT_SYMBOLS: CAPC60X30X40RND; ASSEMBLY_OPTIONS: <ASSEMBLY_OPTIONS>; Agile Part Number: CAP-00142-01; Barcode: 100161; CIP Link: http://xsjbrdwin1/CIP-E/Component/Index/All?pn=100161; Dielectric Type: X5R; Part Type: CERAMIC; Tolerance: 10%; Voltage: 25V
C3063 C3065 C3067 C3069 C3104 C3106 C3108 C3110 C3112 C3114 = CAP_NP: Cap Cer 10uF 20%  6.3V X6S 0402; ALT_SYMBOLS: CAPC100X50X55RND; Agile Part Number: CAP-00035-01; Barcode: 100268; CIP Link: http://xsjbrdwin1/CIP-E/Component/Index/All?pn=100268; Dielectric Type: X6S; Part Type: CERAMIC; Tolerance: 20%; Voltage: 6.3V
C3064 C3066 C3068 C3070 C3105 C3107 C3109 C3111 C3113 C3115 = CAP_NP: Cap Cer 100nF 10% 6.3V X5R 0201; ALT_SYMBOLS: CAPC60X30X33RND; Agile Part Number: CAP-00280-01; Barcode: 10000016; CIP Link: http://xsjbrdwin1/CIP-E/Component/Index/All?pn=10000016; Part Type: --\-\0201 (0603 Metric); Tolerance: 10%; Voltage: 6.3V
C3091 = CAP_NP: Cap Cer 10nF 10% 50V X7R 0402; ALT_SYMBOLS: CAPC100X50X55RND; Agile Part Number: CAP-00031-01; CIP Link: http://xsjbrdwin1/CIP-E/Component/Index/All?pn=100003; Dielectric Type: X7R; OWNER: 4001; PRICE: 0; Part Type: CERAMIC; PartType: CERAMIC; ROHS: Yes; Tolerance: 10%; Voltage: 50VDC; barcode: 100003
DS58 = LED: LED Green Diffused 20mA 5V 570nm 0603; Agile Part Number: DIO-00003-01; Barcode: 300021; CIP Link: http://xsjbrdwin1/CIP-E/Component/Index/All?pn=300021; OWNER: 4001; PRICE: 0.1; Power: 2.2-20MA; ROHS: Yes; Rated Power: 2.2-20MA; Voltage: 2.2V
L157-L161 = BLM15PX121SN1D: Bead 120R 25% 2A 55mR 0402; ALT_SYMBOLS: INDC100X50X55; Agile Part Number: FLT-00035-01; Barcode: 30000051; CIP Link: http://xsjbrdwin1/CIP-E/Component/Index/All?pn=30000051; Part Type: FERRITE; Rated Current: 2A
Q41 = FET-3PIN: MOSFET N-Ch 20V 1.3A 160mR SSOT-3; Agile Part Number: TRN-00012-01; Barcode: 500100; CIP Link: http://xsjbrdwin1/CIP-E/Component/Index/All?pn=500100; OWNER: 4001; PRICE: 0.12; Part Type: FET; PartType: FET; Power: 460MW; ROHS: Yes; Rated Power: 460MW; Rated Voltage: 20V
R298 R299 R301 R331-R339 R341 R344 R924 = RES: Res 4K7 1% 1/16W 100PPM 50V 0402; ALT_SYMBOLS: RESC100X50X40RND; Agile Part Number: RES-00035-01; Barcode: 200067; CIP Link: http://xsjbrdwin1/CIP-E/Component/Index/All?pn=200067; OWNER: 3670; PRICE: 0.01; Part Type: SMT - 1%; PartType: SMT - 1%; Power: 1/16W; ROHS: Yes; Rated Power: 1/16W; Tolerance: 1%; primarykey: 128
R1715 = RES: RES SMD 549 OHM 1% 1/10W 0402; Agile Part Number: RES-00342-01; Barcode: 200378; CIP Link: http://xsjbrdwin1/CIP-E/Component/Index/All?pn=200378; Part Type: SMT - 1%; Rated Power: 1/10W; Tolerance: 1%
R1716 = RES: RES SMD 453 OHM 1% 1/10W 0402; Agile Part Number: RES-00163-01; Barcode: 200167; CIP Link: http://xsjbrdwin1/CIP-E/Component/Index/All?pn=200167; Part Type: SMT - 1%; Rated Power: 1/10W; Tolerance: 1%
R1790 = RES: Res 261R 1% 1/16W 100PPM 50V 0402; ALT_SYMBOLS: RESC100X50X40RND; Agile Part Number: RES-00086-01; Barcode: 200050; CIP Link: http://xsjbrdwin1/CIP-E/Component/Index/All?pn=200050; OWNER: 3501; PRICE: 0; Part Type: SMT - 1%; PartType: SMT - 1%; Power: 1/10W; ROHS: Yes; Rated Power: 1/16W; Tolerance: 1%; primarykey: 60
U43 = SI5382: IC Clk Proc Jitter/Freq 4-In 12-Out 1.8-3.3V I2C/SPI 9x9mm QFN-6; Agile Part Number: ICS-00870-01; Barcode: 50000319; CIP Link: http://xsjbrdwin1/CIP-E/Component/Index/All?pn=50000319; Part Type: CLOCK; Supply Voltage: 1.71V ~ 1.89V, 3.14V ~ 3.47V
U433 = SIT_4PIN: Osc XO 54MHz 3.3V 53PPM 15pF 3225 SMT CMOS with OE; Agile Part Number: OSC-00085-01; Barcode: 60000029; CIP Link: http://xsjbrdwin1/CIP-E/Component/Index/All?pn=60000029; Part Type: OSCILLATOR; RoHS: YES
C1516 C1517 = CAP_NP: Cap Cer 100nF 10% 25V X5R 0402; ALT_SYMBOLS: CAPC100X50X55RND; Agile Part Number: CAP-00068-01; CIP Link: http://xsjbrdwin1/CIP-E/Component/Index/All?pn=100040; Dielectric Type: X5R; OWNER: 4001; PRICE: 0; Part Type: CERAMIC; PartType: CERAMIC; ROHS: Yes; Tolerance: 10%; Voltage: 25V; barcode: 100040
R300 = RES: Res 40R2 1% 1/16W 100PPM 50V 0402; ALT_SYMBOLS: RESC100X50X40RND; Agile Part Number: RES-00045-01; Barcode: 200063; CIP Link: http://xsjbrdwin1/CIP-E/Component/Index/All?pn=200063; OWNER: 3501; PRICE: 0; Part Type: SMT - 1%; PartType: SMT - 1%; Power: 1/10W; ROHS: Yes; Rated Power: 1/16W; Tolerance: 1%; primarykey: 277
U47 = SI570: Osc XO 300MHz 3.3V 61.5PPM 5x7mm SMT LVDS; Agile Part Number: OSC-00027-01; Barcode: 600047; CIP Link: http://xsjbrdwin1/CIP-E/Component/Index/All?pn=600047; OWNER: 3709; PRICE: 33.08; Part Type: OSCILLATOR; PartType: OSCILLATOR; ROHS: YES
U48 = SI570: Osc XO 156.25MHz 3.3V 61.5PPM 5x7mm SMT LVDS; Agile Part Number: OSC-00011-01; Barcode: 600019; CIP Link: http://xsjbrdwin1/CIP-E/Component/Index/All?pn=600019; OWNER: 3709; PRICE: 33.08; Part Type: OSCILLATOR; PartType: OSCILLATOR; ROHS: YES
U130 = SI570_SINGLE: Osc XO 10-280MHz 33.33MHz Default I2C 0x5D 1.8V 61.5PPM 5x7mm SMT CMOS; Agile Part Number: OSC-00028-01; Barcode: 600049; CIP Link: http://xsjbrdwin1/CIP-E/Component/Index/All?pn=600049; Part Type: OSCILLATOR; RoHS: YES
C372 C375-C378 = CAP_NP: Cap Cer 4.7uF 20% 6.3V X5R 0402; ALT_SYMBOLS: CAPC100X50X60RND; Agile Part Number: CAP-00085-01; CIP Link: http://xsjbrdwin1/CIP-E/Component/Index/All?pn=100067; Dielectric Type: X5R; OWNER: 3709; PRICE: 0.06; Part Type: CERAMIC; PartType: CERAMIC; ROHS: Yes; Tolerance: 20%; Voltage: 6.3V; barcode: 100067
DIMMCAGE1 = MECH_SODIMM_CAGE_175: Shield RF 76.2x44.45x8.89mm Unassembled with Vent Holes; Agile Part Number: MEC-00057-01; Barcode: 960011; CIP Link: http://xsjbrdwin1/CIP-E/Component/Index/All?pn=960011; OWNER: 3709; Part Type: Mechanical Part; PartType: SODIMM CAGE; ROHS: 1
J48 = DDR4SODIMM1V2_260P_SMTSKT_STD: Conn DDR4 5.2H SO-DIMM-260 Black SMT; Agile Part Number: CON-00165-01; Barcode: 400104; CIP Link: http://xsjbrdwin1/CIP-E/Component/Index/All?pn=400104; OWNER: 3709; PRICE: 0; Part Type: SHIELDED SO-DIMM; PartType: SHIELDED SO-DIMM; Pins: 204PINS; Pitch: 0.6MM; ROHS: Yes
R330 R340 = RES: Res 100R 1% 1/16W 100PPM 50V 0402; ALT_SYMBOLS: RESC100X50X40RND; Agile Part Number: RES-00046-01; Barcode: 200024; CIP Link: http://xsjbrdwin1/CIP-E/Component/Index/All?pn=200024; OWNER: 4001; PRICE: 0.02; Part Type: SMT - 1%; PartType: SMT - 1%; Power: 1/10W; ROHS: Yes; Rated Power: 1/16W; Tolerance: 1%; primarykey: 12
C379 = CAP_NP: Cap Cer 100uF 20% 4V X6S 0805; ALT_SYMBOLS: CAPC200X125X145RND; ASSEMBLY_OPTIONS: DNP; Agile Part Number: CAP-00038-01; CIP Link: http://xsjbrdwin1/CIP-E/Component/Index/All?pn=100257; Dielectric Type: X6S; OWNER: 3709; PRICE: 0; Part Type: CERAMIC; PartType: CERAMIC; ROHS: Yes; Tolerance: 20%; Voltage: 4V; barcode: 100257
DS54-DS57 = LED: LED Green Diffused 20mA 5V 570nm 0603; Agile Part Number: DIO-00003-01; Barcode: 300021; CIP Link: http://xsjbrdwin1/CIP-E/Component/Index/All?pn=300021; Rated Power: 2.2-20MA; Voltage: 2.2V
R1114-R1117 = RES: Res 261R 1% 1/16W 100PPM 50V 0402; ALT_SYMBOLS: RESC100X50X40RND; Agile Part Number: RES-00086-01; Barcode: 200050; CIP Link: http://xsjbrdwin1/CIP-E/Component/Index/All?pn=200050; Part Type: SMT - 1%; Rated Power: 1/16W; Tolerance: 1%
R1118 = RES: Res 10K 1% 1/16W 100PPM 50V 0402; ALT_SYMBOLS: RESC100X50X40RND; Agile Part Number: RES-00030-01; Barcode: 200025; CIP Link: http://xsjbrdwin1/CIP-E/Component/Index/All?pn=200025; Part Type: SMT - 1%; Rated Power: 1/16W; Tolerance: 1%
SW8 SW13 = PUSHBUTTON-4: Switch SPST-NO Mom 50mA 50V 7.3mm H 100gf SMT; Agile Part Number: SWH-00014-01; Barcode: 440011; CIP Link: http://xsjbrdwin1/CIP-E/Component/Index/All?pn=440011; OWNER: 3709; PRICE: 0.25; Part Type: MOMENT; PartType: MOMENT; ROHS: Yes
U426 = SN74AVC4T245: IC Lvl Trans 4-Bit Bidir 380Mbps 1.2-3.6V 50mA UQFN-16; Agile Part Number: ICS-00049-01; Barcode: 500013; CIP Link: http://xsjbrdwin1/CIP-E/Component/Index/All?pn=500013; Family: BUS TRANSCEIVER; Part Type: BUS TRANSCEIVER; ROHS: Yes

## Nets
GND: C39.2 C361.2 C362.2 C363.2 C364.2 C372.2 C373.2 C374.2 C375.2 C376.2 C377.2 C378.2 C379.2 C380.2 C381.2 C382.2 C383.2 C384.2 C385.2 C386.2 C387.2 C388.2 C389.2 C390.2 C391.2 C1559.2 C1956.2 C1957.2 C3029.2 C3031.2 C3032.2 C3037.2 C3039.2 C3040.2 C3047.1 C3049.1 C3053.2 C3063.2 C3064.2 C3065.2 C3066.2 C3067.2 C3068.2 C3069.2 C3070.2 C3073.2 C3074.2 C3075.2 C3076.2 C3077.2 C3078.2 C3079.2 C3080.2 C3081.2 C3091.2 C3104.2 C3105.2 C3106.2 C3107.2 C3108.2 C3109.2 C3110.2 C3111.2 C3112.2 C3113.2 C3114.2 C3115.2 DIMMCAGE1.1(GND1) DIMMCAGE1.2(GND2) DIMMCAGE1.3(GND3) DIMMCAGE1.4(GND4) DIMMCAGE1.5(GND5) DIMMCAGE1.6(GND6) DIMMCAGE1.7(GND7) DIMMCAGE1.8(GND8) DIMMCAGE1.9(GND9) DIMMCAGE1.10(GND10) DIMMCAGE1.11(GND11) DIMMCAGE1.12(GND12) DIMMCAGE1.13(GND13) DIMMCAGE1.14(GND14) DIMMCAGE1.15(GND15) DIMMCAGE1.16(GND16) DIMMCAGE1.17(GND17) DIMMCAGE1.18(GND18) DIMMCAGE1.19(GND19) J6.2(GND1) J6.3(GND2) J6.4(GND3) J6.5(GND4) J7.2(GND1) J7.3(GND2) J7.4(GND3) J7.5(GND4) J48.1(VSS1) J48.2(VSS2) J48.5(VSS3) J48.6(VSS4) J48.9(VSS5) J48.10(VSS6) J48.14(VSS7) J48.15(VSS8) J48.18(VSS9) J48.19(VSS10) J48.22(VSS11) J48.23(VSS12) J48.26(VSS13) J48.27(VSS14) J48.30(VSS15) J48.31(VSS16) J48.35(VSS17) J48.36(VSS18) J48.39(VSS19) J48.40(VSS20) J48.43(VSS21) J48.44(VSS22) J48.47(VSS23) J48.48(VSS24) J48.51(VSS25) J48.52(VSS26) J48.56(VSS27) J48.57(VSS28) J48.60(VSS29) J48.61(VSS30) J48.64(VSS31) J48.65(VSS32) J48.68(VSS33) J48.69(VSS34) J48.72(VSS35) J48.73(VSS36) J48.77(VSS37) J48.78(VSS38) J48.81(VSS39) J48.82(VSS40) J48.85(VSS41) J48.86(VSS42) J48.89(VSS43) J48.90(VSS44) J48.93(VSS45) J48.94(VSS46) J48.98(VSS47) J48.99(VSS48) J48.102(VSS49) J48.103(VSS50) J48.106(VSS51) J48.107(VSS52) J48.167(VSS53) J48.168(VSS54) J48.171(VSS55) J48.172(VSS56) J48.175(VSS57) J48.176(VSS58) J48.180(VSS59) J48.181(VSS60) J48.184(VSS61) J48.185(VSS62) J48.188(VSS63) J48.189(VSS64) J48.192(VSS65) J48.193(VSS66) J48.196(VSS67) J48.197(VSS68) J48.201(VSS69) J48.202(VSS70) J48.205(VSS71) J48.206(VSS72) J48.209(VSS73) J48.210(VSS74) J48.213(VSS75) J48.214(VSS76) J48.217(VSS77) J48.218(VSS78) J48.222(VSS79) J48.223(VSS80) J48.226(VSS81) J48.227(VSS82) J48.230(VSS83) J48.231(VSS84) J48.234(VSS85) J48.235(VSS86) J48.238(VSS87) J48.239(VSS88) J48.243(VSS89) J48.244(VSS90) J48.247(VSS91) J48.248(VSS92) J48.251(VSS93) J48.252(VSS94) J128.2(GND1) J128.3(GND2) J128.4(GND3) J128.5(GND4) J129.2(GND1) J129.3(GND2) J129.4(GND3) J129.5(GND4) J143.2(GND1) J143.3(GND2) J143.4(GND3) J143.5(GND4) J146.2(GND1) J146.3(GND2) J146.4(GND3) J146.5(GND4) J147.2(GND1) J147.3(GND2) J147.4(GND3) J147.5(GND4) Q41.2(SOURCE) R299.2 R303.2 R321.2 R331.1 R332.1 R333.1 R334.1 R339.1 R340.2 R345.2 R346.2 R1040.2 R1043.2 R1046.2 R1047.2 R1050.2 R1051.2 R1114.2 R1115.2 R1116.2 R1117.2 R1729.2 R1730.2 R1733.2 R1734.2 R1747.2 R1748.2 R1780.2 U43.3(IN_SEL0) U43.4(IN_SEL1) U43.65(GND_PAD) U47.3(GND) U48.3(GND) U130.3(GND) U426.1(1OE_B) U426.10(GND) U426.11(GND) U426.16(2OE_B) U428.1(GND) U428.17(GNDPAD) U430.1(GND) U430.17(GNDPAD) U431.1(GND) U431.17(GNDPAD) U433.2(GND) ; also on sheet 3 4 5 7 8 9 10 11 12 13 14 16 17 18 19 20 21 22 23 24 25 26 27 28 32 33 34 35 43 44 45 46 47 48 49 50 51 52 53 54 55 56 57 58 59 60 61 62 63 64 65 66 67 68 69 70 71 72
VCC1V2: C373.1 C375.1 C376.1 C377.1 C378.1 C379.1 C380.1 C381.1 C382.1 C383.1 C384.1 C385.1 C386.1 C387.1 C388.1 C389.1 J48.111(VDD1) J48.112(VDD2) J48.117(VDD3) J48.118(VDD4) J48.123(VDD5) J48.124(VDD6) J48.129(VDD7) J48.130(VDD8) J48.135(VDD9) J48.136(VDD10) J48.141(VDD11) J48.142(VDD12) J48.147(VDD13) J48.148(VDD14) J48.153(VDD15) J48.154(VDD16) J48.159(VDD17) J48.160(VDD18) J48.163(VDD19) R330.1 R336.1 R337.1 R338.1 R342.1 R343.1 ; also on sheet 4 11 17 25 27 48 59 65 66 67 68
VCC1V8_BUS: C39.1 C1957.1 C3037.1 C3039.1 C3040.1 C3053.1 C3067.1 C3068.1 C3112.1 C3113.1 L158.1 L161.1 R1118.1 SW8.1(P1) SW8.2(P2) SW13.1(P1) SW13.2(P2) U426.3(VCCA) U428.5(VDD) U430.5(VDD) U431.5(VDD) ; also on sheet 4 9 10 12 20 21 22 23 24 25 26 27 34 52 61 62 64
VCC1V8_SI570_33M: C1559.1 C3114.1 C3115.1 L161.2 R924.1 U130.6(VDD)
VCC1V8_SI5381: C361.1 C362.1 C363.1 C3069.1 C3070.1 C3073.1 C3074.1 C3075.1 C3076.1 C3077.1 C3078.1 C3079.1 C3080.1 C3081.1 L158.2 U43.22(VDDO0) U43.26(VDDO1) U43.32(VDD) U43.33(VDDO3) U43.36(VDDO4) U43.40(VDDO5) U43.43(VDDO6) U43.46(VDD) U43.49(VDDO7) U43.52(VDDO8) U43.57(VDDO9) U43.60(VDD)
VCC3V3_SI570_DDR: C390.1 C3106.1 C3107.1 L159.2 R341.1 U47.6(VDD)
VCC3V3_SI570_GT: C391.1 C3108.1 C3109.1 L160.2 R344.1 U48.6(VDD)
VCC3V3_SI5381: C364.1 C3065.1 C3066.1 L157.2 R298.1 R301.1 R322.1 U43.13(VDDA)
VCC3V3_Si5381_XO: C3031.1 C3091.1 U433.1(OE) U433.4(VDD) ; also on sheet 72
VDDO2: U43.29(VDDO2)
8A31004_CLK7_N: C3049.2 U409.J2(CLK7_N)
8A31004_CLK7_P: R1743.1 R1779.2 R1780.1 U409.J1(CLK7_P)
8A34001_CLK0_N: R982.1 U409.B2(CLK0_N) U409.B8(Q0_N)
8A34001_CLK0_P: R982.2 U409.A8(Q0_P) U409.B1(CLK0_P)
8A34001_CLK1_IN_N: R983.1 R1042.2 R1043.1 U409.C2(CLK1_N) ; also on sheet 6
8A34001_CLK1_IN_P: R983.2 R1040.1 R1041.2 U409.C1(CLK1_P) ; also on sheet 6
8A34001_CLK2_IN_N: R1014.1 R1728.2 R1730.1 U409.D2(CLK2_N) ; also on sheet 6
8A34001_CLK2_IN_P: R1014.2 R1727.2 R1729.1 U409.D1(CLK2_P) ; also on sheet 6
8A34001_CLK3_N: C3048.1 R1744.1 R1746.2 R1748.1 U409.E2(CLK3_N)
8A34001_CLK3_P: C3026.1 R1744.2 R1745.2 R1747.1 U409.E1(CLK3_P)
8A34001_CLK3_SMA_N: C3048.2 J143.1(SIG)
8A34001_CLK3_SMA_P: C3026.2 J129.1(SIG)
8A34001_CLK4_IN_N: R986.1 R1732.2 R1734.1 U409.F2(CLK4_N) ; also on sheet 31
8A34001_CLK4_IN_P: R986.2 R1731.2 R1733.1 U409.F1(CLK4_P) ; also on sheet 31
8A34001_CLK5_IN_N: R984.1 R1045.2 R1047.1 U409.G2(CLK5_N) ; also on sheet 28
8A34001_CLK5_IN_P: R984.2 R1044.2 R1046.1 U409.G1(CLK5_P) ; also on sheet 28
8A34001_CLK6_IN_N: R985.1 R1049.2 R1051.1 U409.H2(CLK6_N) ; also on sheet 5
8A34001_CLK6_IN_P: R985.2 R1048.2 R1050.1 U409.H1(CLK6_P) ; also on sheet 5
8A34001_Q1_OUT_C_N: C3051.1 U409.B9(Q1_N)
8A34001_Q1_OUT_C_P: C3050.1 U409.A9(Q1_P)
8A34001_Q1_OUT_N: C3051.2 R1737.1 U428.4(CLK1_B)
8A34001_Q1_OUT_P: C3050.2 R1737.2 U428.3(CLK1)
8A34001_Q2_OUT_C_N: R1774.1 U409.B11(Q2_N)
8A34001_Q2_OUT_C_P: R1773.1 U409.A11(Q2_P)
8A34001_Q2_OUT_N: R1774.2 ; also on sheet 5
8A34001_Q2_OUT_P: R1773.2 ; also on sheet 5
8A34001_Q3_OUT_C_N: R1776.1 U409.B12(Q3_N)
8A34001_Q3_OUT_C_P: R1775.1 U409.A12(Q3_P)
8A34001_Q3_OUT_N: R1776.2 ; also on sheet 5
8A34001_Q3_OUT_P: R1775.2 ; also on sheet 5
8A34001_Q5_OUT_N: C3052.1 U409.L11(Q5_N)
8A34001_Q5_OUT_P: C3027.1 U409.M11(Q5_P)
8A34001_Q5_OUT_SMA_N: C3052.2 J7.1(SIG)
8A34001_Q5_OUT_SMA_P: C3027.2 J6.1(SIG)
8A34001_Q7_OUT_C_N: C3093.1 U409.L8(Q7_N)
8A34001_Q7_OUT_C_P: C3092.1 U409.M8(Q7_P)
8A34001_Q7_OUT_N: C3093.2 R1740.1 U43.2(IN1B)
8A34001_Q7_OUT_P: C3092.2 R1740.2 U43.1(IN1)
8A34001_Q8_OUT_N: U409.B6(Q8_N) ; also on sheet 31
8A34001_Q8_OUT_P: U409.A6(Q8_P) ; also on sheet 31
8A34001_Q9_OUT_N: U409.E11(Q9_N) ; also on sheet 31
8A34001_Q9_OUT_P: U409.E12(Q9_P) ; also on sheet 31
8A34001_Q11_OUT_N: U409.L6(Q11_N) ; also on sheet 6
8A34001_Q11_OUT_P: U409.M6(Q11_P) ; also on sheet 6
8A34001_VDD_CLK0: R1041.1 R1042.1 R1727.1 R1728.1 R1745.1 R1746.1 ; also on sheet 35 71
8A34001_VDD_CLK1: R1044.1 R1045.1 R1048.1 R1049.1 R1731.1 R1732.1 R1779.1 ; also on sheet 35 71
CLK104_AMS_SYSREF_C_N: C3103.2 R1015.1 U430.4(CLK1_B)
CLK104_AMS_SYSREF_C_P: C3102.2 R1015.2 U430.3(CLK1)
CLK104_AMS_SYSREF_N: C3103.1 ; also on sheet 64
CLK104_AMS_SYSREF_P: C3102.1 ; also on sheet 64
CLK104_PL_SYSREF_N: R1735.1 U431.4(CLK1_B) ; also on sheet 64
CLK104_PL_SYSREF_P: R1735.2 U431.3(CLK1) ; also on sheet 64
CPU_RESET: R321.1 SW13.3(P3) SW13.4(P4) ; also on sheet 5
GPIO_LED0_LS: U426.6(1A1) ; also on sheet 5
GPIO_LED1_LS: U426.7(1A2) ; also on sheet 5
GPIO_LED2_LS: U426.8(2A1) ; also on sheet 5
GPIO_LED3_LS: U426.9(2A2) ; also on sheet 5
GPIO_LED_0: DS57.2 U426.15(1B1) ; also on sheet 27
GPIO_LED_1: DS56.2 U426.14(1B2) ; also on sheet 27
GPIO_LED_2: DS55.2 U426.13(2B1)
GPIO_LED_3: DS54.2 U426.12(2B2)
GPIO_SW_PL: R303.1 SW8.3(P3) SW8.4(P4) ; also on sheet 5
MUX_AMS_SYSREF_N: U430.10(Q0_B) ; also on sheet 8
MUX_AMS_SYSREF_P: U430.9(Q0) ; also on sheet 8
MUX_PL_SYSREF_C_N: R1755.1 U431.10(Q0_B)
MUX_PL_SYSREF_C_P: R1754.1 U431.9(Q0)
MUX_PL_SYSREF_N: R1755.2 ; also on sheet 5
MUX_PL_SYSREF_P: R1754.2 ; also on sheet 5
PS_DDR4_SODIMM_A0: J48.144(A0) ; also on sheet 11
PS_DDR4_SODIMM_A1: J48.133(A1) ; also on sheet 11
PS_DDR4_SODIMM_A2: J48.132(A2) ; also on sheet 11
PS_DDR4_SODIMM_A3: J48.131(A3) ; also on sheet 11
PS_DDR4_SODIMM_A4: J48.128(A4) ; also on sheet 11
PS_DDR4_SODIMM_A5: J48.126(A5) ; also on sheet 11
PS_DDR4_SODIMM_A6: J48.127(A6) ; also on sheet 11
PS_DDR4_SODIMM_A7: J48.122(A7) ; also on sheet 11
PS_DDR4_SODIMM_A8: J48.125(A8) ; also on sheet 11
PS_DDR4_SODIMM_A9: J48.121(A9) ; also on sheet 11
PS_DDR4_SODIMM_A10: J48.146(A10/AP) ; also on sheet 11
PS_DDR4_SODIMM_A11: J48.120(A11) ; also on sheet 11
PS_DDR4_SODIMM_A12: J48.119(A12) ; also on sheet 11
PS_DDR4_SODIMM_A13: J48.158(A13) ; also on sheet 11
PS_DDR4_SODIMM_ACT_B: J48.114(ACT_N) ; also on sheet 11
PS_DDR4_SODIMM_ALERT_B: J48.116(ALERT_N) ; also on sheet 11
PS_DDR4_SODIMM_BA0: J48.150(BA0) ; also on sheet 11
PS_DDR4_SODIMM_BA1: J48.145(BA1) ; also on sheet 11
PS_DDR4_SODIMM_BG0: J48.115(BG0) ; also on sheet 11
PS_DDR4_SODIMM_BG1: J48.113(BG1) ; also on sheet 11
PS_DDR4_SODIMM_CAS_B: J48.156(CAS_N/A15) ; also on sheet 11
PS_DDR4_SODIMM_CK0_C: J48.139(CK0_C) ; also on sheet 11
PS_DDR4_SODIMM_CK0_T: J48.137(CK0_T) ; also on sheet 11
PS_DDR4_SODIMM_CK1_C: J48.140(CK1_C/NF) ; also on sheet 11
PS_DDR4_SODIMM_CK1_T: J48.138(CK1_T/NF) ; also on sheet 11
PS_DDR4_SODIMM_CKE0: J48.109(CKE0) R339.2 ; also on sheet 11
PS_DDR4_SODIMM_CKE1: J48.110(CKE1) R331.2 ; also on sheet 11
PS_DDR4_SODIMM_CS0_B: J48.149(CS0_N) ; also on sheet 11
PS_DDR4_SODIMM_CS1_B: J48.157(CS1_N) ; also on sheet 11
PS_DDR4_SODIMM_CS2_B: J48.162(C0/CS2_N/NC) R338.2
PS_DDR4_SODIMM_CS3_B: J48.165(C1/CS3_N/NC) R337.2
PS_DDR4_SODIMM_DM0_B: J48.12(DM0_N/DBI0_N) ; also on sheet 11
PS_DDR4_SODIMM_DM1_B: J48.33(DM1_N/DBI1_N) ; also on sheet 11
PS_DDR4_SODIMM_DM2_B: J48.54(DM2_N/DBI2_N) ; also on sheet 11
PS_DDR4_SODIMM_DM3_B: J48.75(DM3_N/DBI3_N) ; also on sheet 11
PS_DDR4_SODIMM_DM4_B: J48.178(DM4_N/DBI4_N) ; also on sheet 11
PS_DDR4_SODIMM_DM5_B: J48.199(DM5_N/DBI5_N) ; also on sheet 11
PS_DDR4_SODIMM_DM6_B: J48.220(DM6_N/DBI6_N) ; also on sheet 11
PS_DDR4_SODIMM_DM7_B: J48.241(DM7_N/DBI7_N) ; also on sheet 11
PS_DDR4_SODIMM_DQ0: J48.8(DQ0) ; also on sheet 11
PS_DDR4_SODIMM_DQ1: J48.7(DQ1) ; also on sheet 11
PS_DDR4_SODIMM_DQ2: J48.20(DQ2) ; also on sheet 11
PS_DDR4_SODIMM_DQ3: J48.21(DQ3) ; also on sheet 11
PS_DDR4_SODIMM_DQ4: J48.4(DQ4) ; also on sheet 11
PS_DDR4_SODIMM_DQ5: J48.3(DQ5) ; also on sheet 11
PS_DDR4_SODIMM_DQ6: J48.16(DQ6) ; also on sheet 11
PS_DDR4_SODIMM_DQ7: J48.17(DQ7) ; also on sheet 11
PS_DDR4_SODIMM_DQ8: J48.28(DQ8) ; also on sheet 11
PS_DDR4_SODIMM_DQ9: J48.29(DQ9) ; also on sheet 11
PS_DDR4_SODIMM_DQ10: J48.41(DQ10) ; also on sheet 11
PS_DDR4_SODIMM_DQ11: J48.42(DQ11) ; also on sheet 11
PS_DDR4_SODIMM_DQ12: J48.24(DQ12) ; also on sheet 11
PS_DDR4_SODIMM_DQ13: J48.25(DQ13) ; also on sheet 11
PS_DDR4_SODIMM_DQ14: J48.38(DQ14) ; also on sheet 11
PS_DDR4_SODIMM_DQ15: J48.37(DQ15) ; also on sheet 11
PS_DDR4_SODIMM_DQ16: J48.50(DQ16) ; also on sheet 11
PS_DDR4_SODIMM_DQ17: J48.49(DQ17) ; also on sheet 11
PS_DDR4_SODIMM_DQ18: J48.62(DQ18) ; also on sheet 11
PS_DDR4_SODIMM_DQ19: J48.63(DQ19) ; also on sheet 11
PS_DDR4_SODIMM_DQ20: J48.46(DQ20) ; also on sheet 11
PS_DDR4_SODIMM_DQ21: J48.45(DQ21) ; also on sheet 11
PS_DDR4_SODIMM_DQ22: J48.58(DQ22) ; also on sheet 11
PS_DDR4_SODIMM_DQ23: J48.59(DQ23) ; also on sheet 11
PS_DDR4_SODIMM_DQ24: J48.70(DQ24) ; also on sheet 11
PS_DDR4_SODIMM_DQ25: J48.71(DQ25) ; also on sheet 11
PS_DDR4_SODIMM_DQ26: J48.83(DQ26) ; also on sheet 11
PS_DDR4_SODIMM_DQ27: J48.84(DQ27) ; also on sheet 11
PS_DDR4_SODIMM_DQ28: J48.66(DQ28) ; also on sheet 11
PS_DDR4_SODIMM_DQ29: J48.67(DQ29) ; also on sheet 11
PS_DDR4_SODIMM_DQ30: J48.79(DQ30) ; also on sheet 11
PS_DDR4_SODIMM_DQ31: J48.80(DQ31) ; also on sheet 11
PS_DDR4_SODIMM_DQ32: J48.174(DQ32) ; also on sheet 11
PS_DDR4_SODIMM_DQ33: J48.173(DQ33) ; also on sheet 11
PS_DDR4_SODIMM_DQ34: J48.187(DQ34) ; also on sheet 11
PS_DDR4_SODIMM_DQ35: J48.186(DQ35) ; also on sheet 11
PS_DDR4_SODIMM_DQ36: J48.170(DQ36) ; also on sheet 11
PS_DDR4_SODIMM_DQ37: J48.169(DQ37) ; also on sheet 11
PS_DDR4_SODIMM_DQ38: J48.183(DQ38) ; also on sheet 11
PS_DDR4_SODIMM_DQ39: J48.182(DQ39) ; also on sheet 11
PS_DDR4_SODIMM_DQ40: J48.195(DQ40) ; also on sheet 11
PS_DDR4_SODIMM_DQ41: J48.194(DQ41) ; also on sheet 11
PS_DDR4_SODIMM_DQ42: J48.207(DQ42) ; also on sheet 11
PS_DDR4_SODIMM_DQ43: J48.208(DQ43) ; also on sheet 11
PS_DDR4_SODIMM_DQ44: J48.191(DQ44) ; also on sheet 11
PS_DDR4_SODIMM_DQ45: J48.190(DQ45) ; also on sheet 11
PS_DDR4_SODIMM_DQ46: J48.203(DQ46) ; also on sheet 11
PS_DDR4_SODIMM_DQ47: J48.204(DQ47) ; also on sheet 11
PS_DDR4_SODIMM_DQ48: J48.216(DQ48) ; also on sheet 11
PS_DDR4_SODIMM_DQ49: J48.215(DQ49) ; also on sheet 11
PS_DDR4_SODIMM_DQ50: J48.228(DQ50) ; also on sheet 11
PS_DDR4_SODIMM_DQ51: J48.229(DQ51) ; also on sheet 11
PS_DDR4_SODIMM_DQ52: J48.211(DQ52) ; also on sheet 11
PS_DDR4_SODIMM_DQ53: J48.212(DQ53) ; also on sheet 11
PS_DDR4_SODIMM_DQ54: J48.224(DQ54) ; also on sheet 11
PS_DDR4_SODIMM_DQ55: J48.225(DQ55) ; also on sheet 11
PS_DDR4_SODIMM_DQ56: J48.237(DQ56) ; also on sheet 11
PS_DDR4_SODIMM_DQ57: J48.236(DQ57) ; also on sheet 11
PS_DDR4_SODIMM_DQ58: J48.249(DQ58) ; also on sheet 11
PS_DDR4_SODIMM_DQ59: J48.250(DQ59) ; also on sheet 11
PS_DDR4_SODIMM_DQ60: J48.232(DQ60) ; also on sheet 11
PS_DDR4_SODIMM_DQ61: J48.233(DQ61) ; also on sheet 11
PS_DDR4_SODIMM_DQ62: J48.245(DQ62) ; also on sheet 11
PS_DDR4_SODIMM_DQ63: J48.246(DQ63) ; also on sheet 11
PS_DDR4_SODIMM_DQS0_C: J48.11(DQS0_C) ; also on sheet 11
PS_DDR4_SODIMM_DQS0_T: J48.13(DQS0_T) ; also on sheet 11
PS_DDR4_SODIMM_DQS1_C: J48.32(DQS1_C) ; also on sheet 11
PS_DDR4_SODIMM_DQS1_T: J48.34(DQS1_T) ; also on sheet 11
PS_DDR4_SODIMM_DQS2_C: J48.53(DQS2_C) ; also on sheet 11
PS_DDR4_SODIMM_DQS2_T: J48.55(DQS2_T) ; also on sheet 11
PS_DDR4_SODIMM_DQS3_C: J48.74(DQS3_C) ; also on sheet 11
PS_DDR4_SODIMM_DQS3_T: J48.76(DQS3_T) ; also on sheet 11
PS_DDR4_SODIMM_DQS4_C: J48.177(DQS4_C) ; also on sheet 11
PS_DDR4_SODIMM_DQS4_T: J48.179(DQS4_T) ; also on sheet 11
PS_DDR4_SODIMM_DQS5_C: J48.198(DQS5_C) ; also on sheet 11
PS_DDR4_SODIMM_DQS5_T: J48.200(DQS5_T) ; also on sheet 11
PS_DDR4_SODIMM_DQS6_C: J48.219(DQS6_C) ; also on sheet 11
PS_DDR4_SODIMM_DQS6_T: J48.221(DQS6_T) ; also on sheet 11
PS_DDR4_SODIMM_DQS7_C: J48.240(DQS7_C) ; also on sheet 11
PS_DDR4_SODIMM_DQS7_T: J48.242(DQS7_T) ; also on sheet 11
PS_DDR4_SODIMM_EVENT_B: J48.134(EVENT_N/NF) R336.2
PS_DDR4_SODIMM_ODT0: J48.155(ODT0) ; also on sheet 11
PS_DDR4_SODIMM_ODT1: J48.161(ODT1) ; also on sheet 11
PS_DDR4_SODIMM_PARITY: J48.143(PARITY) ; also on sheet 11
PS_DDR4_SODIMM_RAS_B: J48.152(RAS_N/A16) ; also on sheet 11
PS_DDR4_SODIMM_SA0: J48.256(SA0) R335.2
PS_DDR4_SODIMM_SA1: J48.260(SA1) R333.2
PS_DDR4_SODIMM_SA2: J48.166(SA2) R332.2
PS_DDR4_SODIMM_SCL: J48.253(SCL) ; also on sheet 23
PS_DDR4_SODIMM_SDA: J48.254(SDA) ; also on sheet 23
PS_DDR4_SODIMM_WE_B: J48.151(WE_N/A14) ; also on sheet 11
PS_DDR4_VTT: J48.258(VTT) ; also on sheet 59
PS_REF_CLK: R300.2 ; also on sheet 10
Si570_PS_REF_CLK: R300.1 U130.4(OUT)
SI5381_ADC_REFCLK_C_N: C3057.1 U43.34(OUT3B)
SI5381_ADC_REFCLK_C_P: C3056.1 U43.35(OUT3)
SI5381_ADC_REFCLK_N: C3057.2 ; also on sheet 7
SI5381_ADC_REFCLK_P: C3056.2 ; also on sheet 7
SI5381_AMS_SYSREF_C_N: C3097.2 R987.1 U430.7(CLK0_B)
SI5381_AMS_SYSREF_C_P: C3096.2 R987.2 U430.6(CLK0)
SI5381_AMS_SYSREF_N: C3097.1 U43.23(OUT0B)
SI5381_AMS_SYSREF_P: C3096.1 U43.24(OUT0)
SI5381_CLK2_IN_N: R1741.1 U43.15(IN2B) ; also on sheet 5
SI5381_CLK2_IN_P: R1741.2 U43.14(IN2) ; also on sheet 5
SI5381_CLK104_MUX_SEL: U430.2(CLK_SEL) U431.2(CLK_SEL) ; also on sheet 5
SI5381_CLK_125_C_N: C3101.1 U43.50(OUT7B)
SI5381_CLK_125_C_P: C3100.1 U43.51(OUT7)
SI5381_CLK_125_N: C3101.2 ; also on sheet 5
SI5381_CLK_125_P: C3100.2 ; also on sheet 5
SI5381_DAC_REFCLK_C_N: C3055.1 U43.20(OUT0AB)
SI5381_DAC_REFCLK_C_P: C3054.1 U43.21(OUT0A)
SI5381_DAC_REFCLK_N: C3055.2 ; also on sheet 8
SI5381_DAC_REFCLK_P: C3054.2 ; also on sheet 8
SI5381_FEEDBACK_IN_N: C3072.2 R1742.1 U43.62(IN3B)
SI5381_FEEDBACK_IN_P: C3071.2 R1742.2 U43.61(IN3)
SI5381_FEEDBACK_N: C3072.1 U43.58(OUT9AB)
SI5381_FEEDBACK_P: C3071.1 U43.59(OUT9A)
SI5381_GTR_REF_CLK_N: U43.37(OUT4B) ; also on sheet 12
SI5381_GTR_REF_CLK_P: U43.38(OUT4) ; also on sheet 12
SI5381_GTR_REFCLK_USB3_N: U43.44(OUT6B) ; also on sheet 12
SI5381_GTR_REFCLK_USB3_P: U43.45(OUT6) ; also on sheet 12
SI5381_INT_ALM: R322.2 U43.12(INTRB) ; also on sheet 22
SI5381_PL_CLK_C_N: C1789.1 U43.41(OUT5B)
SI5381_PL_CLK_C_P: C1788.1 U43.42(OUT5)
SI5381_PL_CLK_N: C1789.2 ; also on sheet 4
SI5381_PL_CLK_P: C1788.2 ; also on sheet 4
SI5381_PL_SYSREF_C_N: C3095.2 R1736.1 U431.7(CLK0_B)
SI5381_PL_SYSREF_C_P: C3094.2 R1736.2 U431.6(CLK0)
SI5381_PL_SYSREF_N: C3095.1 U43.27(OUT1B)
SI5381_PL_SYSREF_P: C3094.1 U43.28(OUT1)
SI5381_SCL: U43.16(SCLK) ; also on sheet 23
SI5381_SDA: U43.18(SDA_SDIO) ; also on sheet 23
SI53340_MUX_GT_SEL: U428.2(CLK_SEL) ; also on sheet 5
USER_MGT_REFCLK_N: U428.10(Q0_B) ; also on sheet 6
USER_MGT_REFCLK_P: U428.9(Q0) ; also on sheet 6
USER_MGT_SI570_C_CLOCK_N: C1516.1 U48.5(OUT_B)
USER_MGT_SI570_C_CLOCK_P: C1517.1 U48.4(OUT)
USER_MGT_SI570_CLOCK_N: C1516.2 R1738.1 U428.7(CLK0_B)
USER_MGT_SI570_CLOCK_P: C1517.2 R1738.2 U428.6(CLK0)
USER_MGT_SI570_SCL: U48.8(SCL) ; also on sheet 23
USER_MGT_SI570_SDA: U48.7(SDA) ; also on sheet 23
USER_SI570_C0_N: C392.2 R342.2 R345.1 ; also on sheet 4
USER_SI570_C0_P: C393.2 R343.2 R346.1 ; also on sheet 4
USER_SI570_C0_SCL: U47.8(SCL) ; also on sheet 23
USER_SI570_C0_SDA: U47.7(SDA) ; also on sheet 23
USER_SI570_C_C0_N: C392.1 U47.5(OUT_B)
USER_SI570_C_C0_P: C393.1 U47.4(OUT)
USER_SI570_PSREFCLK_SCL: U130.8(SCL) ; also on sheet 23
USER_SI570_PSREFCLK_SDA: U130.7(SDA) ; also on sheet 23
UTIL_2V5: C372.1 J48.257(VPP1) J48.259(VPP2) ; also on sheet 26 47 49 65 66 67 68
UTIL_3V3: C1956.1 C3063.1 C3064.1 C3104.1 C3105.1 C3110.1 C3111.1 J48.255(VDDSPD) L157.1 L159.1 L160.1 R335.1 R1790.1 U426.2(VCCB) ; also on sheet 9 10 20 22 23 24 25 26 27 28 29 30 31 33 34 43 44 45 47 49 51 53 54 55 56 57 59 60 61 64
VREF_PS_SODIMM: C374.1 J48.164(VREFCA) R330.2 R340.1
ZYNQ_DDR4_SODIMM_RESET_B: J48.108(RESET_N) R334.2 ; also on sheet 11
N21442938: R341.2 U47.2(OE)
N21443734: R344.2 U48.2(OE)
N25926886: R924.2 U130.2(OE)
N30562839: C3030.2 U43.8(XA)
N30562889: C3029.1 R1715.2
N30562901: C3028.2 C3030.1 R1715.1 R1716.2
N30563221: C3028.1 R1716.1 U433.3(OUT)
N30564848: C3032.1 U43.9(XB)
N30732521: C3036.1 U43.54(OUT8)
N30918110: DS54.1 R1114.1
N30918112: DS55.1 R1115.1
N30918114: DS56.1 R1116.1
N30918116: DS57.1 R1117.1
N30919815: R1118.2 U426.4(1DIR) U426.5(2DIR)
N31080595: R301.2 U43.39(I2C_SEL)
N31080768: R299.1 U43.17(A1_SDO) U43.19(A0_CSB)
N31321992: C3035.1 J146.1(SIG)
N31321994: C3035.2 U43.63(IN0)
N31357829: R298.2 U43.6(RSTB)
N31358406: C3047.2 U43.64(IN0B)
N31420495: C3036.2 J147.1(SIG)
N31478988: J128.1(SIG) R1743.2
N33232389: Q41.1(GATE) U43.47(RSVD)
N33232689: DS58.2 R1790.2
N33232691: DS58.1 Q41.3(DRAIN)

Not connected (* = marked no-connect by the designer): J48 87(CB5/NC)* 88(CB4/NC)* 91(CB1/NC)* 92(CB0/NC)* 95(DQS8_C)* 96(DM8_N/DBI8_N/NC)* 97(DQS8_T)* 100(CB6/NC)* 101(CB2/NC)* 104(CB7/NC)* 105(CB3/NC)*; U43 5(PDNB) 7(X1) 10(X2) 11(OEB) 25(RSVD) 30(OUT2B) 31(OUT2) 48(RSVD) 53(OUT8B) 55(OUT9B) 56(OUT9); U47 1(NC)*; U48 1(NC)*; U130 1(NC1)* 5(NC2)*; U409 H11(Q10_N)* H12(Q10_P)* L9(Q6_N)* L12(Q4_N)* M9(Q6_P)* M12(Q4_P)*; U428 8(NC)* 11(Q1)* 12(Q1_B)* 13(Q2)* 14(Q2_B)* 15(Q3)* 16(Q3_B)*; U430 8(NC)* 11(Q1)* 12(Q1_B)* 13(Q2)* 14(Q2_B)* 15(Q3)* 16(Q3_B)*; U431 8(NC)* 11(Q1)* 12(Q1_B)* 13(Q2)* 14(Q2_B)* 15(Q3)* 16(Q3_B)*

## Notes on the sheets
sheet 36
- AC caps in cage
- DAC T0
- AMS_SYSREF MUX
- PL_SYSREF MUX
- 3G ADC Tile0/1
- 1588
- GTR_REF
- Bank88 SyncE
- PL_CLOCK
- GTR_REF_USB
- Default:IN0
- CLK_125
sheet 38
- GTY0 SyncE
- Default 0:CLK0
- GTY1 SyncE
- Bank88 1PPS
- Bank67
- GTY1 REFCLK MUX
- FMC+
- FMC+
- Bank88
- Si5381
- FMC+
- FMC+
- GTY1 REFCLK
- INPUT
  1PPS
- OUTPUT
- INPUT
sheet 39
- CLK104 AC ==>
- Default 0:PCLK0
- CLK104 DC ==>
- Default 0:PCLK0
sheet 41
- PS SODIMM DECOUPLING
sheet 42
- 300MHz LVDS
- 156.25MHz LVDS
- 33.333333...
  (33 + 1/3 MHz)
